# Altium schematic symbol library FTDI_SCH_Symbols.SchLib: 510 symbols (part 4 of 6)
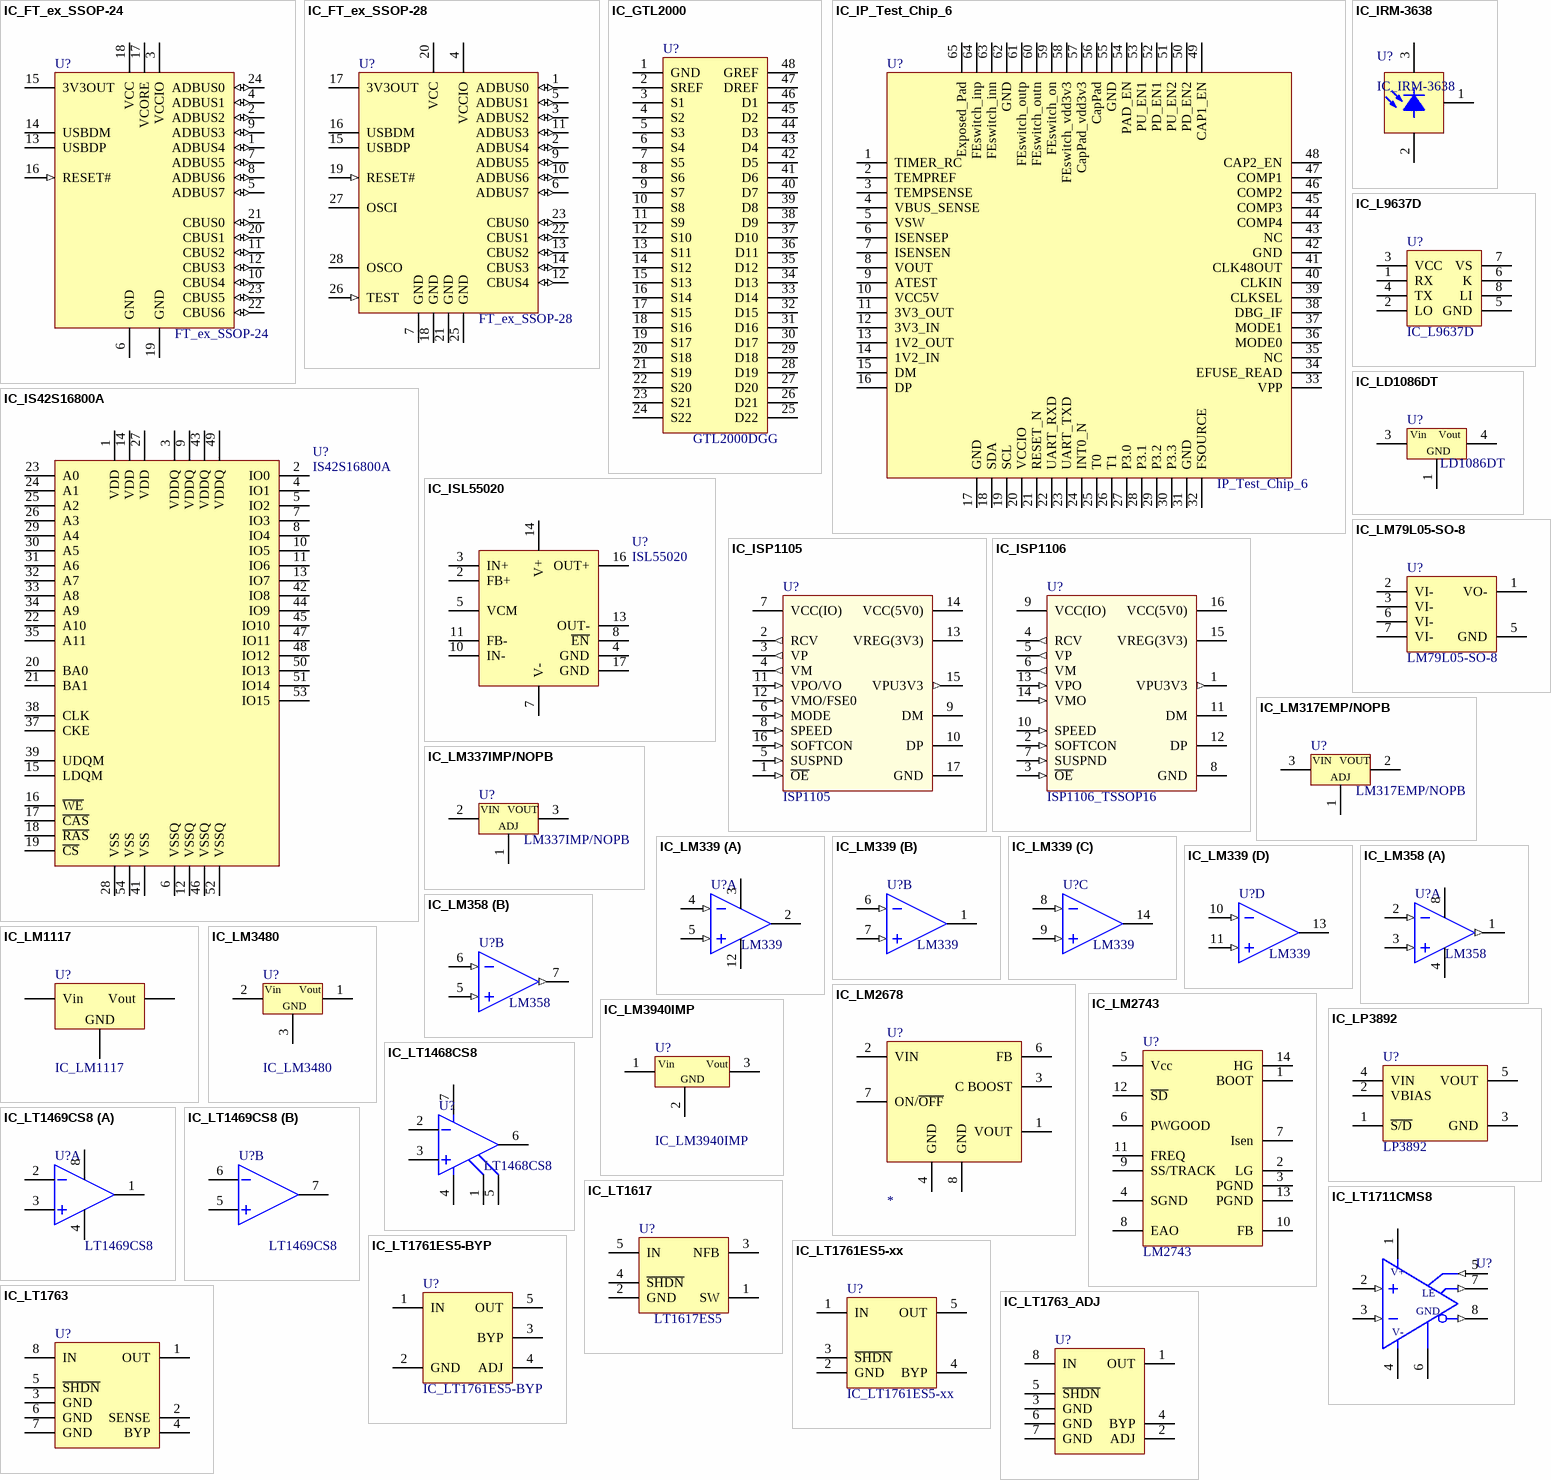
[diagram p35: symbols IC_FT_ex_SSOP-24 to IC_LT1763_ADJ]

## IC_IP_Test_Chip_6
designator U?, comment IP_Test_Chip_6
FTDI IP Test Chip 6
footprint SO-24N (SOIC, 24-Leads, Body 15.4x7.5mm, Pitch 1.27mm, IPC Medium Density)
footprint TSOP65P640X120-24N (TSOP, 24-Leads, Body 7.9x4.5mm (max), Pitch 0.65mm, IPC Medium Density)
pins: 1 TIMER_RC, 2 TEMPREF, 3 TEMPSENSE, 4 VBUS_SENSE, 5 VSW, 6 ISENSEP, 7 ISENSEN, 8 VOUT, 9 ATEST, 10 VCC5V, 11 3V3_OUT, 12 3V3_IN, 13 1V2_OUT, 14 1V2_IN, 15 DM, 16 DP, 17 GND, 18 SDA, 19 SCL, 20 VCCIO, 21 RESET_N, 22 UART_RXD, 23 UART_TXD, 24 INT0_N, 25 T0, 26 T1, 27 P3.0, 28 P3.1, 29 P3.2, 30 P3.3, 31 GND, 32 FSOURCE, 33 VPP, 34 EFUSE_READ, 35 NC, 36 MODE0, 37 MODE1, 38 DBG_IF, 39 CLKSEL, 40 CLKIN, 41 CLK48OUT, 42 GND, 43 NC, 44 COMP4, 45 COMP3, 46 COMP2, 47 COMP1, 48 CAP2_EN, 49 CAP1_EN, 50 PD_EN2, 51 PU_EN2, 52 PD_EN1, 53 PU_EN1, 54 PAD_EN, 55 GND, 56 CapPad, 57 CapPad_vdd3v3, 58 FEswitch_vdd3v3, 59 FEswitch_on, 60 FEswitch_outn, 61 FEswitch_outp, 62 GND, 63 FEswitch_inn, 64 FEswitch_inp, 65 Exposed_Pad

## IC_IRM-3638
designator U?
Infrared Remote Control Receiver; 38kHz
footprint IRM-3638 (Infrared remote control receiver)
pins: 1 OUT, 2 GND, 3 Vcc

## IC_IS42S16800A
designator U?, comment IS42S16800A
8 Meg x 16, 128-MBIT SYNCHRONOUS DRAM
footprint TSOP80P1180X120-54N (TSOP, 54-Leads, Body 22.4x10.3mm (max), Pitch 0.80mm, IPC Medium Density)
pins: 1 VDD, 2 IO0, 3 VDDQ, 4 IO1, 5 IO2, 6 VSSQ, 7 IO3, 8 IO4, 9 VDDQ, 10 IO5, 11 IO6, 12 VSSQ, 13 IO7, 14 VDD, 15 LDQM, 16 ~{WE}, 17 ~{CAS}, 18 ~{RAS}, 19 ~{CS}, 20 BA0, 21 BA1, 22 A10, 23 A0, 24 A1, 25 A2, 26 A3, 27 VDD, 28 VSS, 29 A4, 30 A5, 31 A6, 32 A7, 33 A8, 34 A9, 35 A11, 36 NC hidden, 37 CKE, 38 CLK, 39 UDQM, 40 NC hidden, 41 VSS, 42 IO8, 43 VDDQ, 44 IO9, 45 IO10, 46 VSSQ, 47 IO11, 48 IO12, 49 VDDQ, 50 IO13, 51 IO14, 52 VSSQ, 53 IO15, 54 VSS

## IC_ISL55020
designator U?, comment ISL55020
Wideband, Low Distortion, Differential  Amplifier
footprint QFN65P400X400X100-16M (QFN, 16-Leads, Body 4.0x4.0mm (max), Pitch 0.65mm, IPC Low Density)
pins: 2 FB+, 3 IN+, 4 GND, 5 VCM, 7 V-, 8 ~{EN}, 10 IN-, 11 FB-, 13 OUT-, 14 V+, 16 OUT+, 17 GND

## IC_ISP1105
designator U?, comment ISP1105
USB Transceiver
pins: 1 ~{OE} (in), 2 RCV (out), 3 VP (out), 4 VM (out), 5 SUSPND (in), 6 MODE (in), 7 VCC(IO) (power), 8 SPEED (in), 9 DM, 10 DP, 11 VPO/VO (in), 12 VMO/FSE0 (in), 13 VREG(3V3) (power), 14 VCC(5V0) (power), 15 VPU3V3 (out), 16 SOFTCON (in), 17 GND (power)

## IC_ISP1106
designator U?, comment ISP1106_TSSOP16
Advanced Universal Serial Bus transceiver; TSSOP-16
footprint TSSOP127P600-16N
pins: 1 VPU3V3 (out), 2 SOFTCON (in), 3 ~{OE} (in), 4 RCV (out), 5 VP (out), 6 VM (out), 7 SUSPND (in), 8 GND (power), 9 VCC(IO) (power), 10 SPEED (in), 11 DM, 12 DP, 13 VPO (in), 14 VMO (in), 15 VREG(3V3) (power), 16 VCC(5V0) (power)

## IC_L9637D
designator U?
ISO 9141 INTERFACE
footprint SO-8N (8-Pin Small Outline Integrated Circuit 1.27 mm Pitch, IPC Medium Density)
pins: 1 RX, 2 LO, 3 VCC, 4 TX, 5 GND, 6 K, 7 VS, 8 LI

## IC_LD1086DT
designator U?, comment LD1086DT
LDO Voltage Regulator; 1.5A; DPAK-3
footprint DPAK-3N (D-PAK, 3-Pads, Body 6.2x6.6mm (max), IPC Medium Density)
pins: 1 GND, 3 Vin, 4 Vout

## IC_LM79L05-SO-8
designator U?, comment LM79L05-SO-8
footprint SO-8_N (8-Pin Small Outline Integrated Circuit 1.27 mm Pitch, IPC Medium Density)
pins: 1 VO-, 2 VI-, 3 VI-, 4 NC hidden, 5 GND, 6 VI-, 7 VI-, 8 NC hidden

## IC_LM317EMP/NOPB
designator U?, comment LM317EMP/NOPB
3-Terminal Adjustable Positive Regulator; Manufacturer: National Semiconductor; Note: IC REG POSITIVE ADJ 1A SOT223
footprint SOT223P700X180-3N (SOT223, 4-Leads, Body 6.7x7.3mm (max), Pitch 2.30mm, IPC Medium Density)
pins: 1 ADJ, 2 Vout, 3 Vin

## IC_LM337IMP/NOPB
designator U?, comment LM337IMP/NOPB
3-Terminal Adjustable Negative Regulator; Manufacturer: National Semiconductor; Note: IC VREG NEGATIVE ADJ 1A SOT223
footprint SOT223P700X180-3N (SOT223, 4-Leads, Body 6.7x7.3mm (max), Pitch 2.30mm, IPC Medium Density)
pins: 1 ADJ, 2 Vin, 3 Vout

## IC_LM339
designator U?, comment LM339
Low power dual operational amplifier; Manufacturer: Analog Devices; ManufacturerPartNo: AD8033AR
footprint TSOP65P640X110-14N (TSOP, 14-Leads, Body 5.1x4.5mm (max), Pitch 0.65mm, IPC Medium Density)
part A pins: 2 OUT1 (oc), 3 VCC, 4 IN-1 (in), 5 IN+1 (in), 12 VSS
part B pins: 1 OUT2 (oc), 6 IN-2 (in), 7 IN+2 (in)
part C pins: 8 IN-3 (in), 9 IN+3 (in), 14 OUT3 (oc)
part D pins: 10 IN-4 (in), 11 IN+4 (in), 13 OUT4 (oc)

## IC_LM358
designator U?, comment LM358
Low power dual operational amplifier; Manufacturer: Analog Devices; ManufacturerPartNo: AD8033AR
footprint SO-8N (8-Pin Small Outline Integrated Circuit 1.27 mm Pitch, IPC Medium Density)
part A pins: 1 OUT1 (out), 2 IN-1 (in), 3 IN+1 (in), 4 VSS, 8 VCC
part B pins: 5 IN+2 (in), 6 IN-2 (in), 7 OUT2 (out)

## IC_LM1117
designator U?
0.8A Voltage Regulator
footprint SOT223P700X180-4N (SOT223, 4-Leads, Body 6.7x7.3mm (max), Pitch 2.30mm, IPC Medium Density)
footprint TO252P955X203-3N (D-PAK, 3-Pads, Body 6.3x6.2mm (max), IPC Medium Density); pin to pad 2>4
pins: 1 GND, 2 Vout, 3 Vin, 4 Vout hidden

## IC_LM2678
designator U?
SIMPLE SWITCHER® High Efficiency 5A Step-Down  Voltage Regulator
footprint TO-263-7 (TO-263-7pin SMT package)
footprint TO-263-7 (TO-263-7pin SMT package)
pins: 1 VOUT, 2 VIN, 3 C BOOST, 4 GND, 6 FB, 7 ON/~{OFF}, 8 GND

## IC_LM2743
designator U?, comment LM2743
Low Voltage N-Channel MOSFET Synchronous Buck  Regulator Controller
footprint TSSOP-14
pins: 1 BOOT, 2 LG, 3 PGND, 4 SGND, 5 Vcc, 6 PWGOOD, 7 Isen, 8 EAO, 9 SS/TRACK, 10 FB, 11 FREQ, 12 ~{SD}, 13 PGND, 14 HG

## IC_LM3480
designator U?
100 mA, SOT-23, Quasi Low-Dropout Linear Voltage  Regulator
footprint SOT23-3AL (SOT23 SMT Package)
pins: 1 Vout, 2 Vin, 3 GND

## IC_LM3940IMP
designator U?
1A Voltage Regulator
footprint SOT223P700X180-4N (SOT223, 4-Leads, Body 6.7x7.3mm (max), Pitch 2.30mm, IPC Medium Density)
footprint TO252P955X203-3N (D-PAK, 3-Pads, Body 6.3x6.2mm (max), IPC Medium Density); pin to pad 2>4 4>2
pins: 1 Vin, 2 GND, 3 Vout, 4 GND hidden to GND

## IC_LP3892
designator U?, comment LP3892
1.5A; LDO
footprint PSOP8
pins: 1 ~{S/D}, 2 VBIAS, 3 GND, 4 VIN, 5 VOUT

## IC_LT1468CS8
designator U?, comment LT1468CS8
90MHz, 22V/µs  16-Bit Accurate  Operational Amplifi er; Manufacturer: Linear Technology; Note: 4.5ns Single/Dual Supply  3V/5V Comparator with  Rail-to-Rail Output
footprint SO-8N (8-Pin Small Outline Integrated Circuit 1.27 mm Pitch, IPC Medium Density)
pins: 1 NULL, 2 +IN, 3 -IN, 4 VEE, 5 NULL, 6 OUT, 7 VCC, 8 DNC hidden

## IC_LT1469CS8
designator U?, comment LT1469CS8
Dual 90MHz, 22V/us  16-Bit Accurate Operational Amplifier; Manufacturer: Linear Technology
footprint SO-8N (8-Pin Small Outline Integrated Circuit 1.27 mm Pitch, IPC Medium Density)
part A pins: 1 OUTA, 2 -INA, 3 +INA, 4 V-, 8 V+
part B pins: 5 IN+B, 6 IN-B, 7 OUTB

## IC_LT1617
designator U?, comment LT1617ES5
Micropower Inverting DC/DC Converter in SOT-23
footprint SOT23-5AL (SOT23, 5-Leads, Body 2.9x1.6mm, Pitch 0.95mm, Lead Span 2.8mm)
pins: 1 SW, 2 GND, 3 NFB, 4 ~{SHDN}, 5 IN

## IC_LT1711CMS8
designator U?
Single, 4.5ns, 3V/5V/±5V,  Rail-to-Rail Comparator; Manufacturer: Analog Devices; ManufacturerPartNo: AD8033AR
footprint SOP65P400X130-8N (SOP, 8-Leads, Body 3.2x2.9mm (max), Pitch 0.65mm, IPC Medium Density)
pins: 1 V+ (power), 2 IN+ (in), 3 IN- (in), 4 V- (power), 5 LE (in), 6 GND (power), 7 Q (out), 8 ~{Q} (out)

## IC_LT1761ES5-BYP
designator U?
Adjustable output; 100mA; LDO Micropower  Regulator in SOT-23
footprint SOT23-5AL (SOT23, 5-Leads, Body 2.9x1.6mm, Pitch 0.95mm, Lead Span 2.8mm, IPC High Density)
pins: 1 IN, 2 GND (power), 3 BYP, 4 ADJ, 5 OUT

## IC_LT1761ES5-xx
designator U?
100mA; LDO Micropower  Regulators in SOT-23
footprint SOT23-5AL (SOT23, 5-Leads, Body 2.9x1.6mm, Pitch 0.95mm, Lead Span 2.8mm, IPC High Density)
pins: 1 IN, 2 GND (power), 3 ~{SHDN}, 4 BYP, 5 OUT

## IC_LT1763
designator U?
500mA; LDO Micropower  Regulator
footprint SO-8_N (8-Pin Small Outline Integrated Circuit 1.27 mm Pitch, IPC Medium Density)
pins: 1 OUT, 2 SENSE, 3 GND (power), 4 BYP, 5 ~{SHDN}, 6 GND (power), 7 GND (power), 8 IN

## IC_LT1763_ADJ
designator U?
500mA; LDO Micropower  Regulator
footprint SO-8_N (8-Pin Small Outline Integrated Circuit 1.27 mm Pitch, IPC Medium Density)
pins: 1 OUT, 2 ADJ, 3 GND (power), 4 BYP, 5 ~{SHDN}, 6 GND (power), 7 GND (power), 8 IN

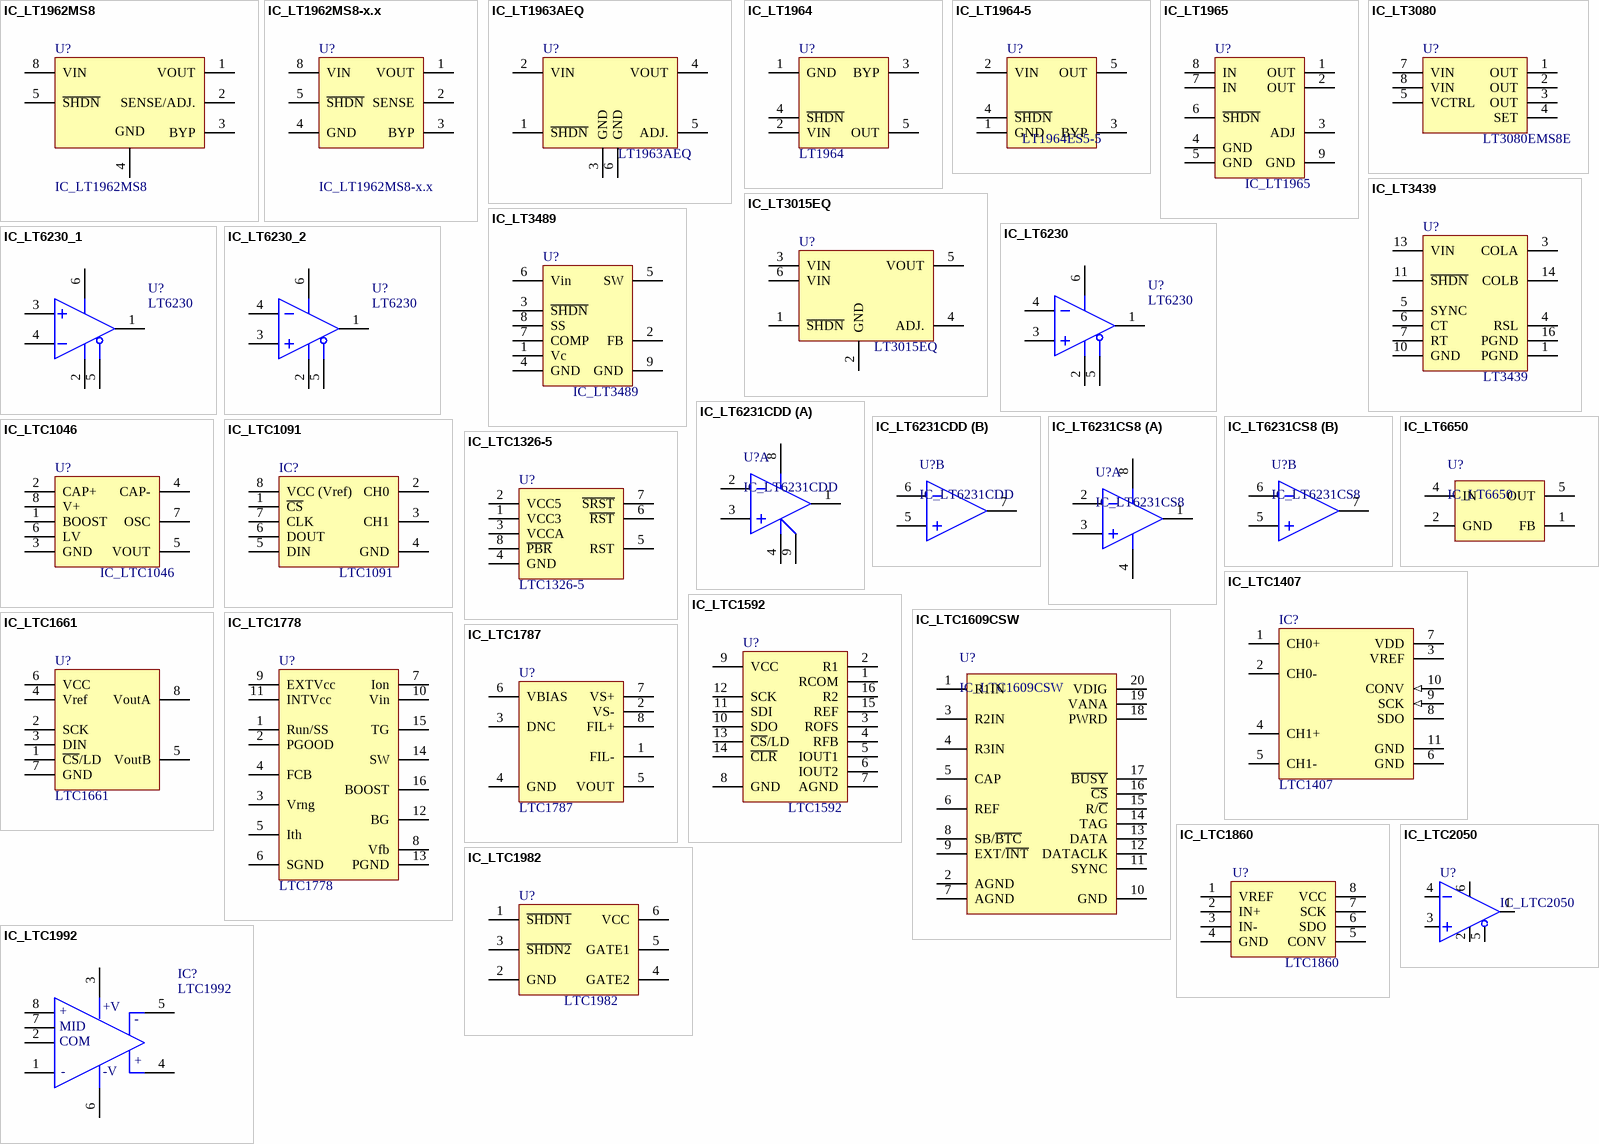
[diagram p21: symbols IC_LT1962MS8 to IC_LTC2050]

## IC_LT1962MS8
designator U?
Adjustable Output; 300mA, Low Noise,  Micropower  LDO Regulator
footprint MSOP65P490X110-8N (MSOP, 8-Leads, Body 3.1x3.1mm (max), Pitch 0.65mm, IPC Medium Density)
pins: 1 VOUT, 2 SENSE/ADJ. (power), 3 BYP, 4 GND, 5 ~{SHDN}, 6 NC hidden, 7 NC hidden, 8 VIN

## IC_LT1962MS8-x.x
designator U?
300mA, Low Noise,  Micropower  LDO Regulators
footprint MSOP65P490X110-8N (MSOP, 8-Leads, Body 3.1x3.1mm (max), Pitch 0.65mm, IPC Medium Density)
pins: 1 VOUT, 2 SENSE (power), 3 BYP, 4 GND, 5 ~{SHDN}, 6 NC hidden, 7 NC hidden, 8 VIN

## IC_LT1963AEQ
designator U?, comment LT1963AEQ
1.5A, Low Noise,  Fast Transient Response  LDO Regulator
footprint DPAK-3N (D-PAK, 3-Pads, Body 6.2x6.6mm (max), IPC Medium Density)
pins: 1 ~{SHDN}, 2 VIN, 3 GND, 4 VOUT, 5 ADJ. (power), 6 GND

## IC_LT1964
designator U?, comment LT1964
200mA, Low Noise,  Low Dropout Negative  Micropower Regulator in ThinSOT
footprint SOT23-5AL (SOT23, 5-Leads, Body 2.9x1.6mm, Pitch 0.95mm, Lead Span 2.8mm)
pins: 1 GND, 2 VIN (power), 3 BYP, 4 ~{SHDN}, 5 OUT

## IC_LT1964-5
designator U?, comment LT1964ES5-5
200mA, Low Noise,  Low Dropout Negative  Micropower Regulator
footprint SOT23-5AL (SOT23, 5-Leads, Body 2.9x1.6mm, Pitch 0.95mm, Lead Span 2.8mm)
pins: 1 GND, 2 VIN, 3 BYP, 4 ~{SHDN}, 5 OUT

## IC_LT1965
designator U?
pins: 1 OUT, 2 OUT, 3 ADJ, 4 GND, 5 GND, 6 ~{SHDN}, 7 IN, 8 IN, 9 GND

## IC_LT3015EQ
designator U?, comment LT3015EQ
1.5A, Low Noise,  Negative Linear Regulator  with Precision Current Limit
footprint DPAK-3N (D-PAK, 3-Pads, Body 6.2x6.6mm (max), IPC Medium Density)
pins: 1 ~{SHDN}, 2 GND, 3 VIN, 4 ADJ. (power), 5 VOUT, 6 VIN

## IC_LT3080
designator U?, comment LT3080EMS8E
Adjustable,1.1A, Single Resistor, Low Dropout Regulator
footprint MSOP65P510X110_HS-8N (MSOP, 8-Leads, Body 3.1x3.1mm (max), Pitch 0.65mm, IPC Medium Density)
pins: 1 OUT (power), 2 OUT (power), 3 OUT (power), 4 SET, 5 VCTRL (power), 6 NC hidden, 7 VIN (power), 8 VIN (power), 9 OUT

## IC_LT3439
designator U?, comment LT3439
Slew Rate Controlled  Ultralow Noise1A Isolated  DC/DC Transformer Driver
footprint TSSOP65P640X120-16N (TSOP, 16-Leads, Body 5.1x4.5mm (max), Pitch 0.65mm, IPC Medium Density)
pins: 1 PGND, 2 NC hidden, 3 COLA, 4 RSL, 5 SYNC, 6 CT, 7 RT, 8 NC hidden, 9 NC hidden, 10 GND, 11 ~{SHDN}, 12 NC hidden, 13 VIN, 14 COLB, 15 NC hidden, 16 PGND

## IC_LT3489
designator U?
pins: 1 Vc, 2 FB, 3 ~{SHDN}, 4 GND, 5 SW, 6 Vin, 7 COMP, 8 SS, 9 GND

## IC_LT6230
designator U?, comment LT6230
215MHz, Rail-to-Rail Output, 3.5mA Op Amp Family
footprint SOT23-6N (SOT23, 6-Leads, Body 3.0x3.0mm (max), Pitch 0.95mm, IPC Medium Density)
pins: 1 OUT, 2 V-, 3 IN+, 4 IN-, 5 ~{EN}, 6 V+

## IC_LT6230_1
designator U?, comment LT6230
215MHz, Rail-to-Rail Output, 3.5mA Op Amp Family
footprint SOT23-6N (SOT23, 6-Leads, Body 3.0x3.0mm (max), Pitch 0.95mm, IPC Medium Density)
pins: 1 OUT, 2 V-, 3 IN+, 4 IN-, 5 ~{EN}, 6 V+

## IC_LT6230_2
designator U?, comment LT6230
215MHz, Rail-to-Rail Output, 3.5mA Op Amp Family
footprint SOT23-6N (SOT23, 6-Leads, Body 3.0x3.0mm (max), Pitch 0.95mm, IPC Medium Density)
pins: 1 OUT, 2 V-, 3 IN+, 4 IN-, 5 ~{EN}, 6 V+

## IC_LT6231CDD
designator U?
215MHz, Rail-to-Rail Output, 3.5mA Op Amp Family
footprint QFN50P300X300X85-8N (QFN, 8-Leads, Body 3.1x3.1mm (max), Pitch 0.50mm, IPC Medium Density)
part A pins: 1 OUTA, 2 -IN A, 3 +IN A, 4 V-, 8 V+, 9 PAD
part B pins: 5 +IN B, 6 -IN B, 7 OUT B

## IC_LT6231CS8
designator U?
215MHz, Rail-to-Rail Output, 3.5mA Op Amp Family
footprint QFN50P300X300X85-8N (QFN, 8-Leads, Body 3.1x3.1mm (max), Pitch 0.50mm, IPC Medium Density)
part A pins: 1 OUTA, 2 -IN A, 3 +IN A, 4 V-, 8 V+
part B pins: 5 +IN B, 6 -IN B, 7 OUT B

## IC_LT6650
designator U?
Micropower, 400mV  Reference with Rail-to-Rail  Buffer Amplifier in SOT-23
footprint SOT23-5AL (SOT23, 5-Leads, Body 2.9x1.6mm, Pitch 0.95mm, Lead Span 2.8mm)
pins: 1 FB, 2 GND, 3 NC hidden, 4 IN, 5 OUT

## IC_LTC1046
designator U?
50mA monolithic CMOS switched  capacitor voltage converter
footprint SO-8_N (8-Pin Small Outline Integrated Circuit 1.27 mm Pitch, IPC Medium Density)
pins: 1 BOOST (power), 2 CAP+ (power), 3 GND (power), 4 CAP- (power), 5 VOUT (power), 6 LV (power), 7 OSC (power), 8 V+ (power)

## IC_LTC1091
designator IC?, comment LTC1091
Serial 12-Bit/14-Bit, 3Msps  Simultaneous Sampling  ADCs with Shutdown
footprint SO-8N (8-Pin Small Outline Integrated Circuit 1.27 mm Pitch, IPC Medium Density)
pins: 1 ~{CS}, 2 CH0, 3 CH1, 4 GND, 5 DIN, 6 DOUT (power), 7 CLK (power), 8 VCC (Vref) (oc)

## IC_LTC1326-5
designator U?, comment LTC1326-5
Tripple Voltage Controller
pins: 1 VCC3, 2 VCC5, 3 VCCA, 4 GND, 5 RST, 6 ~{RST}, 7 ~{SRST}, 8 ~{PBR}

## IC_LTC1407
designator IC?, comment LTC1407
Serial 12-Bit/14-Bit, 3Msps  Simultaneous Sampling  ADCs with Shutdown
footprint SOP127P600-8N_w_thermal_pad
pins: 1 CH0+, 2 CH0-, 3 VREF, 4 CH1+, 5 CH1-, 6 GND (power), 7 VDD (power), 8 SDO (oc), 9 SCK (in), 10 CONV (in), 11 GND (power)

## IC_LTC1592
designator U?, comment LTC1592
16-Bit SoftSpan DAC  with Programmable Output Range
footprint SSOP63P600X175-16N (SOP, 16-Leads, Body 5.0x4.0mm (max), Pitch 0.63mm, IPC Medium Density)
pins: 1 RCOM, 2 R1, 3 ROFS, 4 RFB, 5 IOUT1, 6 IOUT2, 7 AGND, 8 GND, 9 VCC, 10 SDO, 11 SDI, 12 SCK, 13 ~{CS}/LD, 14 ~{CLR}, 15 REF, 16 R2

## IC_LTC1609CSW
designator U?
16-Bit, 200ksps, Serial ADC  with Multiple Input Ranges
pins: 1 R1IN, 2 AGND, 3 R2IN, 4 R3IN, 5 CAP, 6 REF, 7 AGND, 8 SB/~{BTC}, 9 EXT/~{INT}, 10 GND, 11 SYNC, 12 DATACLK, 13 DATA, 14 TAG, 15 R/~{C}, 16 ~{CS}, 17 ~{BUSY}, 18 PWRD, 19 VANA, 20 VDIG

## IC_LTC1661
designator U?, comment LTC1661
Micropower Dual  10-Bit DAC in MSOP
footprint MSOP65P490X96-8N (MSOP, 8-Leads, Body 3.1x3.1mm (max), Pitch 0.65mm, IPC Medium Density)
pins: 1 ~{CS}/LD, 2 SCK, 3 DIN, 4 Vref, 5 VoutB, 6 VCC, 7 GND, 8 VoutA

## IC_LTC1778
designator U?, comment LTC1778
Wide Operating Range,  No RSENSE (TM) Step-Down Controller
footprint SOP63P600X173-16N (SOP, 16-Leads, Body 5.0x4.0mm (max), Pitch 0.63mm, IPC Medium Density)
pins: 1 Run/SS, 2 PGOOD, 3 Vrng, 4 FCB, 5 Ith, 6 SGND, 7 Ion, 8 Vfb, 9 EXTVcc, 10 Vin, 11 INTVcc, 12 BG, 13 PGND, 14 SW, 15 TG, 16 BOOST

## IC_LTC1787
designator U?, comment LTC1787
Precision, High Side  Current Sense Amplifiers
footprint MSOP-08
pins: 1 FIL-, 2 VS-, 3 DNC, 4 GND, 5 VOUT, 6 VBIAS, 7 VS+, 8 FIL+

## IC_LTC1860
designator U?, comment LTC1860
Serial 12-Bit/14-Bit, 3.5Msps  Sampling ADCs with Shutdown
pins: 1 VREF, 2 IN+, 3 IN-, 4 GND, 5 CONV, 6 SDO, 7 SCK, 8 VCC

## IC_LTC1982
designator U?, comment LTC1982
Dual Micropower High Side Switch Controller in SOT-23
footprint SOT23-6N (SOT23, 6-Leads, Body 3.0x3.0mm (max), Pitch 0.95mm, IPC Medium Density)
pins: 1 ~{SHDN1}, 2 GND, 3 ~{SHDN2}, 4 GATE2, 5 GATE1, 6 VCC

## IC_LTC1992
designator IC?, comment LTC1992
Low Power, Fully Differential  Input/Output  Amplifier/Driver Family
footprint SOT23-8AL (SOT23 8-PIN 0.65mm PITCH)
pins: 1 IN-, 2 VCOM, 3 +VS, 4 OUT+, 5 OUT-, 6 -VS, 7 VMID, 8 IN+

## IC_LTC2050
designator U?
Zero-Drift Operational Amplifier in SOT-23
footprint SOT23-6N (SOT23, 6-Leads, Body 3.0x3.0mm (max), Pitch 0.95mm, IPC Medium Density)
pins: 1 OUT, 2 V-, 3 IN+, 4 IN-, 5 ~{SHDN} (power), 6 V+

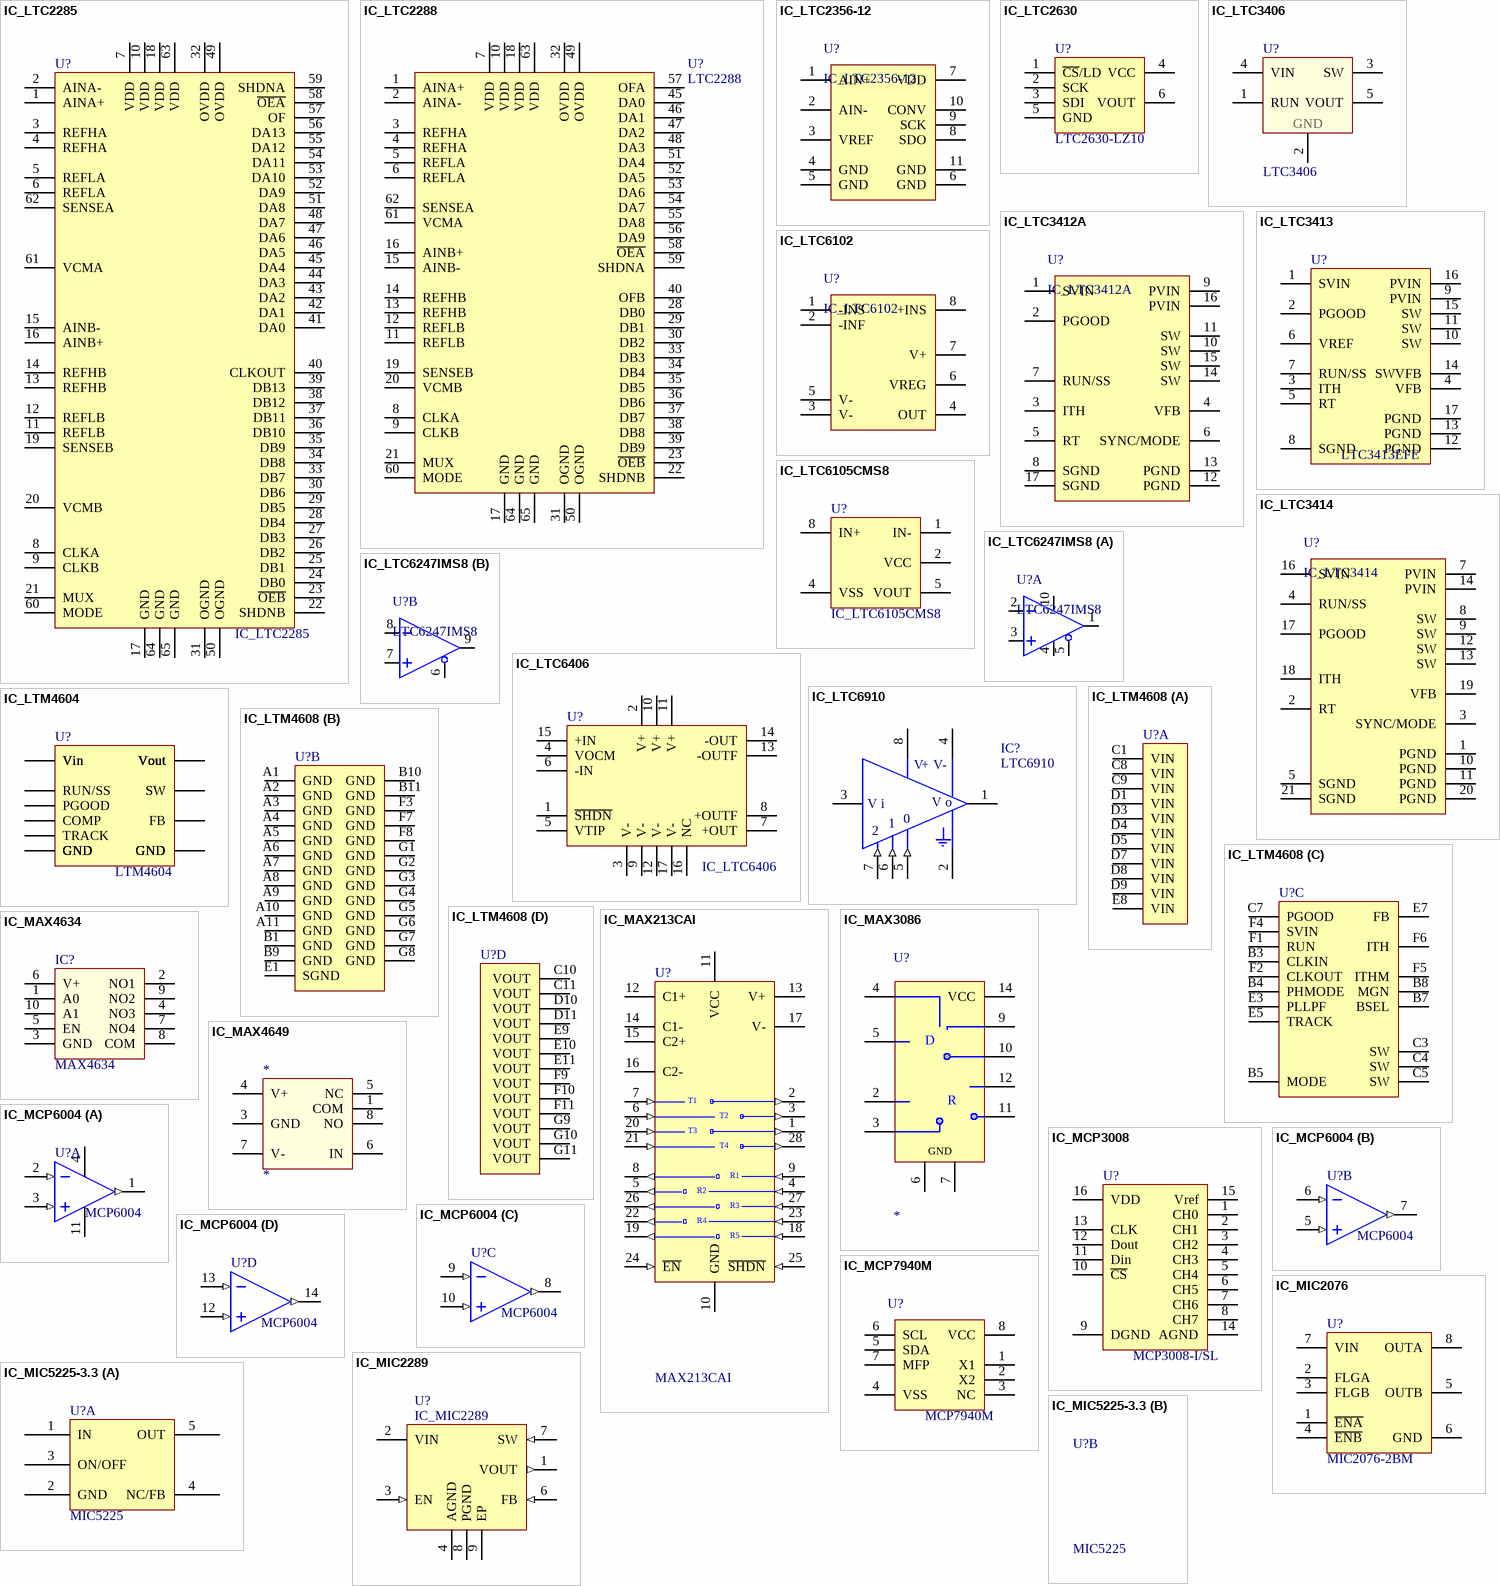
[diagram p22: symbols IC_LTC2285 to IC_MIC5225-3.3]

## IC_LTC2285
designator U?
Dual 14-Bit, 125Msps Low Power 3V ADC
footprint QFN50P900X900X80-64M (QFN, 64-Leads, Body 9.1x9.1mm (max), Pitch 0.50mm, IPC Low Density)
pins: 1 AINA+, 2 AINA-, 3 REFHA, 4 REFHA, 5 REFLA, 6 REFLA, 7 VDD, 8 CLKA, 9 CLKB, 10 VDD, 11 REFLB, 12 REFLB, 13 REFHB, 14 REFHB, 15 AINB-, 16 AINB+, 17 GND, 18 VDD, 19 SENSEB, 20 VCMB, 21 MUX, 22 SHDNB, 23 ~{OEB}, 24 DB0, 25 DB1, 26 DB2, 27 DB3, 28 DB4, 29 DB5, 30 DB6, 31 OGND, 32 OVDD, 33 DB7, 34 DB8, 35 DB9, 36 DB10, 37 DB11, 38 DB12, 39 DB13, 40 CLKOUT, 41 DA0, 42 DA1, 43 DA2, 44 DA3, 45 DA4, 46 DA5, 47 DA6, 48 DA7, 49 OVDD, 50 OGND, 51 DA8, 52 DA9, 53 DA10, 54 DA11, 55 DA12, 56 DA13, 57 OF, 58 ~{OEA}, 59 SHDNA, 60 MODE, 61 VCMA, 62 SENSEA, 63 VDD, 64 GND, 65 GND

## IC_LTC2288
designator U?, comment LTC2288
Dual 10-Bit, 65/40/25Msps  Low Noise 3V ADC
footprint QFN50P900X900X80-64M (QFN, 64-Leads, Body 9.1x9.1mm (max), Pitch 0.50mm, IPC Low Density)
pins: 1 AINA+, 2 AINA-, 3 REFHA, 4 REFHA, 5 REFLA, 6 REFLA, 7 VDD, 8 CLKA, 9 CLKB, 10 VDD, 11 REFLB, 12 REFLB, 13 REFHB, 14 REFHB, 15 AINB-, 16 AINB+, 17 GND, 18 VDD, 19 SENSEB, 20 VCMB, 21 MUX, 22 SHDNB, 23 ~{OEB}, 24 NC hidden, 25 NC hidden, 26 NC hidden, 27 NC hidden, 28 DB0, 29 DB1, 30 DB2, 31 OGND, 32 OVDD, 33 DB3, 34 DB4, 35 DB5, 36 DB6, 37 DB7, 38 DB8, 39 DB9, 40 OFB, 41 NC hidden, 42 NC hidden, 43 NC hidden, 44 NC hidden, 45 DA0, 46 DA1, 47 DA2, 48 DA3, 49 OVDD, 50 OGND, 51 DA4, 52 DA5, 53 DA6, 54 DA7, 55 DA8, 56 DA9, 57 OFA, 58 ~{OEA}, 59 SHDNA, 60 MODE, 61 VCMA, 62 SENSEA, 63 VDD, 64 GND, 65 GND

## IC_LTC2356-12
designator U?
Serial 12-Bit/14-Bit, 3.5Msps  Sampling ADCs with Shutdown
pins: 1 AIN+, 2 AIN-, 3 VREF, 4 GND, 5 GND, 6 GND, 7 VDD, 8 SDO, 9 SCK, 10 CONV, 11 GND

## IC_LTC2630
designator U?, comment LTC2630-LZ10
Single 10-Bit  Rail-to- Rail DACs with 10ppm/°C  Reference in SC70
footprint SC70-0.65mm_pitch-6N (SC70, 6-Leads, Body 2.2x2.4mm (max), Pitch 0.65mm, IPC Medium Density)
pins: 1 ~{CS}/LD, 2 SCK, 3 SDI, 4 VCC, 5 GND, 6 VOUT

## IC_LTC3406
designator U?, comment LTC3406
1.5MHz, 600mA  Synchronous Step-Down  Regulator in ThinSOT
footprint SOT23-5AL (SOT23, 5-Leads, Body 2.9x1.6mm, Pitch 0.95mm, Lead Span 2.8mm)
pins: 1 RUN, 2 GND, 3 SW, 4 VIN, 5 VOUT

## IC_LTC3412A
designator U?
3A, 4MHz, Monolithic  Synchronous Step-Down Regulator
pins: 1 SVIN, 2 PGOOD, 3 ITH, 4 VFB, 5 RT, 6 SYNC/MODE, 7 RUN/SS, 8 SGND, 9 PVIN, 10 SW, 11 SW, 12 PGND, 13 PGND, 14 SW, 15 SW, 16 PVIN, 17 SGND

## IC_LTC3413
designator U?, comment LTC3413EFE
3A, 2MHz Monolithic  Synchronous Regulator for  DDR/QDR Memory Termination
footprint TSSOP65P640X110_HS-16N (TSOP, 16-Leads, Body 5.1x4.5mm (max), Pitch 0.65mm, IPC Medium Density)
pins: 1 SVIN (power), 2 PGOOD (power), 3 ITH (power), 4 VFB (power), 5 RT (power), 6 VREF (power), 7 RUN/SS (power), 8 SGND (power), 9 PVIN (power), 10 SW (power), 11 SW (power), 12 PGND (power), 13 PGND (power), 14 SWVFB (power), 15 SW (power), 16 PVIN (power), 17 PGND (power)

## IC_LTC3414
designator U?
4A, 4MHz, Monolithic  Synchronous Step-Down Regulator
pins: 1 PGND, 2 RT, 3 SYNC/MODE, 4 RUN/SS, 5 SGND, 6 NC hidden, 7 PVIN, 8 SW, 9 SW, 10 PGND, 11 PGND, 12 SW, 13 SW, 14 PVIN, 15 NC hidden, 16 SVIN, 17 PGOOD, 18 ITH, 19 VFB, 20 PGND, 21 SGND

## IC_LTC6102
designator U?
Precision Zero Drift Current Sense Amplifier
pins: 1 -INS, 2 -INF, 3 V-, 4 OUT, 5 V-, 6 VREG, 7 V+, 8 +INS

## IC_LTC6105CMS8
designator U?
Precision, Extended Input Range Current Sense Amplifier, Linear Technology
pins: 1 IN- (power), 2 VCC (power), 3 NC (power) hidden, 4 VSS (power), 5 VOUT (power), 6 NC (power) hidden, 7 NC (power) hidden, 8 IN+ (power)

## IC_LTC6247IMS8
designator U?, comment LTC6247IMS8
180MHz, 1mA Power  Efficient Rail-to-Rail  I/O Op Amps
footprint MSOP50P490X120-10N (MSOP, 10-Leads, Body 3.1x3.1mm (max), Pitch 0.50mm, IPC Medium Density)
part A pins: 1 OUTA, 2 INA-, 3 INA+, 4 V-, 5 ~{SHDNA} (power), 10 V+
part B pins: 6 ~{SHDNB} (power), 7 INB+, 8 INB-, 9 OUTB

## IC_LTC6406
designator U?
3GHz, Low Noise, Rail-to-Rail Input Differential Amplifier/Driver
pins: 1 ~{SHDN} (power), 2 V+ (power), 3 V- (power), 4 VOCM (power), 5 VTIP (power), 6 -IN (power), 7 +OUT (power), 8 +OUTF (power), 9 V- (power), 10 V+ (power), 11 V+ (power), 12 V- (power), 13 -OUTF (power), 14 -OUT (power), 15 +IN (power), 16 NC (power), 17 V- (power)

## IC_LTC6910
designator IC?, comment LTC6910
Digitally Controlled  Programmable  Gain Amplifiers in SOT-23
footprint SOT23-8AL (SOT23 8-PIN 0.65mm PITCH)
pins: 1 VOUT, 2 AGND (power), 3 VIN, 4 V- (power), 5 G0 (in), 6 G1 (in), 7 G2 (in), 8 V+ (power)

## IC_LTM4604
designator U?, comment LTM4604
footprint LGA1500X900X245 (uModule, LGA, 77-Leads, Body 15.0x9.0mm,  Pitch 1.27mm, Linear Technology)
pins: A1 GND, A2 GND, A3 GND, A4 GND, A5 GND, A6 GND, A7 GND, A8 GND, A9 GND, A10 GND, A11 GND, B1 Vin, B3 SW, B4 SW, B6 GND, B7 GND, B8 GND, B9 GND, B10 GND, B11 GND, C1 Vin, C3 Vin, C4 Vin, C5 Vin, C6 Vin, C7 Vin, C8 GND, C9 GND, C10 GND, C11 GND, D1 RUN/SS, D7 Vin, D8 Vout, D9 Vout, D10 Vout, D11 Vout, E1 TRACK, E4 GND, E5 GND, E6 Vin, E7 Vin, E8 Vout, E9 Vout, E10 Vout, E11 Vout, F1 PGOOD, F3 GND, F4 GND, F5 GND, F6 Vout, F7 Vout, F8 Vout, F9 Vout, F10 Vout, F11 Vout, G1 COMP, G2 FB, G3 GND, G4 GND, G5 GND, G6 Vout, G7 Vout, G8 Vout, G9 Vout, G10 Vout, G11 Vout

## IC_LTM4608
designator U?
Low VIN, 8A DC/DC  uModule with Tracking, Margining,  and Frequency Synchronization
part A pins: C1 VIN, C8 VIN, C9 VIN, D1 VIN, D3 VIN, D4 VIN, D5 VIN, D7 VIN, D8 VIN, D9 VIN, E8 VIN
part B pins: A1 GND, A2 GND, A3 GND, A4 GND, A5 GND, A6 GND, A7 GND, A8 GND, A9 GND, A10 GND, A11 GND, B1 GND, B9 GND, B10 GND, B11 GND, E1 SGND, F3 GND, F7 GND, F8 GND, G1 GND, G2 GND, G3 GND, G4 GND, G5 GND, G6 GND, G7 GND, G8 GND
part C pins: B3 CLKIN, B4 PHMODE, B5 MODE, B7 BSEL, B8 MGN, C3 SW, C4 SW, C5 SW, C7 PGOOD, E3 PLLPF, E5 TRACK, E7 FB, F1 RUN, F2 CLKOUT, F4 SVIN, F5 ITHM, F6 ITH
part D pins: C10 VOUT, C11 VOUT, D10 VOUT, D11 VOUT, E9 VOUT, E10 VOUT, E11 VOUT, F9 VOUT, F10 VOUT, F11 VOUT, G9 VOUT, G10 VOUT, G11 VOUT

## IC_MAX213CAI
designator U?, comment MAX213CAI
+5V RS-232 Transceiver with 0.1µF External Capacitor; Note: Pins 18, 19, 22 and 23 are active in SHUTDOWN.
footprint SSOP28 (SSOP; 28 Leads; Body Width 5.3 mm; Pitch 0.65 mm)
3D model SSOP28 (SSOP; 28 Leads; Body Width 5.3 mm; Pitch 0.65 mm)
pins: 1 T3OUT (out), 2 T1OUT (out), 3 T2OUT (out), 4 R2IN (in), 5 R2OUT (out), 6 T2IN (in), 7 T1IN (in), 8 R1OUT (out), 9 R1IN (in), 10 GND (power), 11 VCC (power), 12 C1+, 13 V+ (power), 14 C1-, 15 C2+, 16 C2-, 17 V- (power), 18 R5IN (in), 19 R5OUT (out), 20 T3IN (in), 21 T4IN (in), 22 R4OUT (out), 23 R4IN (in), 24 ~{EN} (in), 25 ~{SHDN} (in), 26 R3OUT (out), 27 R3IN (in), 28 T4OUT (out)

## IC_MAX3086
designator U?
RS422 Transceiver
footprint SO-14_N (14-Pin Small Outline Integrated Circuit 1.27 mm Pitch, IPC Medium Density)
pins: 1 NC hidden, 2 RO, 3 ~{RE}, 4 DE, 5 DI, 6 GND, 7 GND, 8 NC hidden, 9 Y, 10 Z, 11 B, 12 A, 13 NC hidden, 14 VCC

## IC_MAX4634
designator IC?, comment MAX4634
Fast, Low-Voltage, 4 Ohm,  4-Channel CMOS Analog Multiplexer
footprint TSSOP50P490X110-10N (TSSOP, 10-Leads, Body 3.0x3.0mm (max), Pitch 0.50mm, IPC Medium Density)
pins: 1 A0, 2 NO1, 3 GND, 4 NO3, 5 EN, 6 V+, 7 NO4, 8 COM, 9 NO2, 10 A1

## IC_MAX4649
designator *
pins: 1 COM, 2 NC hidden, 3 GND, 4 V+, 5 NC, 6 IN, 7 V-, 8 NO

## IC_MCP3008
designator U?, comment MCP3008-I/SL
2.7V 8-Channel 10-Bit A/D Converter  with SPI Serial Interface
footprint SO-16N (16-Pin Small Outline Integrated Circuit 1.27 mm Pitch, IPC Medium Density)
pins: 1 CH0, 2 CH1, 3 CH2, 4 CH3, 5 CH4, 6 CH5, 7 CH6, 8 CH7, 9 DGND, 10 ~{CS}, 11 Din, 12 Dout, 13 CLK, 14 AGND, 15 Vref, 16 VDD

## IC_MCP6004
designator U?, comment MCP6004
IC OPAMP GP 1MHZ RRO 14SOIC; Manufacturer: Microchip Technology; ManufacturerPartNo: MCP6004-I/SL
footprint TSOP65P640X110-14N (TSOP, 14-Leads, Body 5.1x4.5mm (max), Pitch 0.65mm, IPC Medium Density)
part A pins: 1 OUT1 (out), 2 IN-1 (in), 3 IN+1 (in), 4 VDD, 11 VSS
part B pins: 5 IN+2 (in), 6 IN-2 (in), 7 OUT2 (out)
part C pins: 8 OUT3 (out), 9 IN-3 (in), 10 IN+3 (in)
part D pins: 12 IN+4 (in), 13 IN-4 (in), 14 OUT4 (out)

## IC_MCP7940M
designator U?, comment MCP7940M
Low-Cost I2C Real-Time Clock/Calendar with SRAM
pins: 1 X1, 2 X2, 3 NC, 4 VSS, 5 SDA, 6 SCL, 7 MFP, 8 VCC

## IC_MIC2076
designator U?, comment MIC2076-2BM
USB Power distribution switch; 500mA
footprint SO-8_N (8-Pin Small Outline Integrated Circuit 1.27 mm Pitch, IPC Medium Density)
pins: 1 ~{ENA}, 2 FLGA, 3 FLGB, 4 ~{ENB}, 5 OUTB, 6 GND, 7 VIN, 8 OUTA

## IC_MIC2289
designator U?
White LED Driver; Manufacturer: Micrel Inc; ManufacturePartNo: MIC2289-34YML TR; Value: MIC2289-34; Note: IC LED DRIVER WHITE BCKLGT 8-MLF
footprint MLF8
pins: 1 VOUT (out), 2 VIN (power), 3 EN (in), 4 AGND (power), 5 NC hidden, 6 FB (in), 7 SW (in), 8 PGND (power), 9 EP

## IC_MIC5225-3.3
designator U?, comment MIC5225
part A pins: 1 IN, 2 GND, 3 ON/OFF, 4 NC/FB, 5 OUT

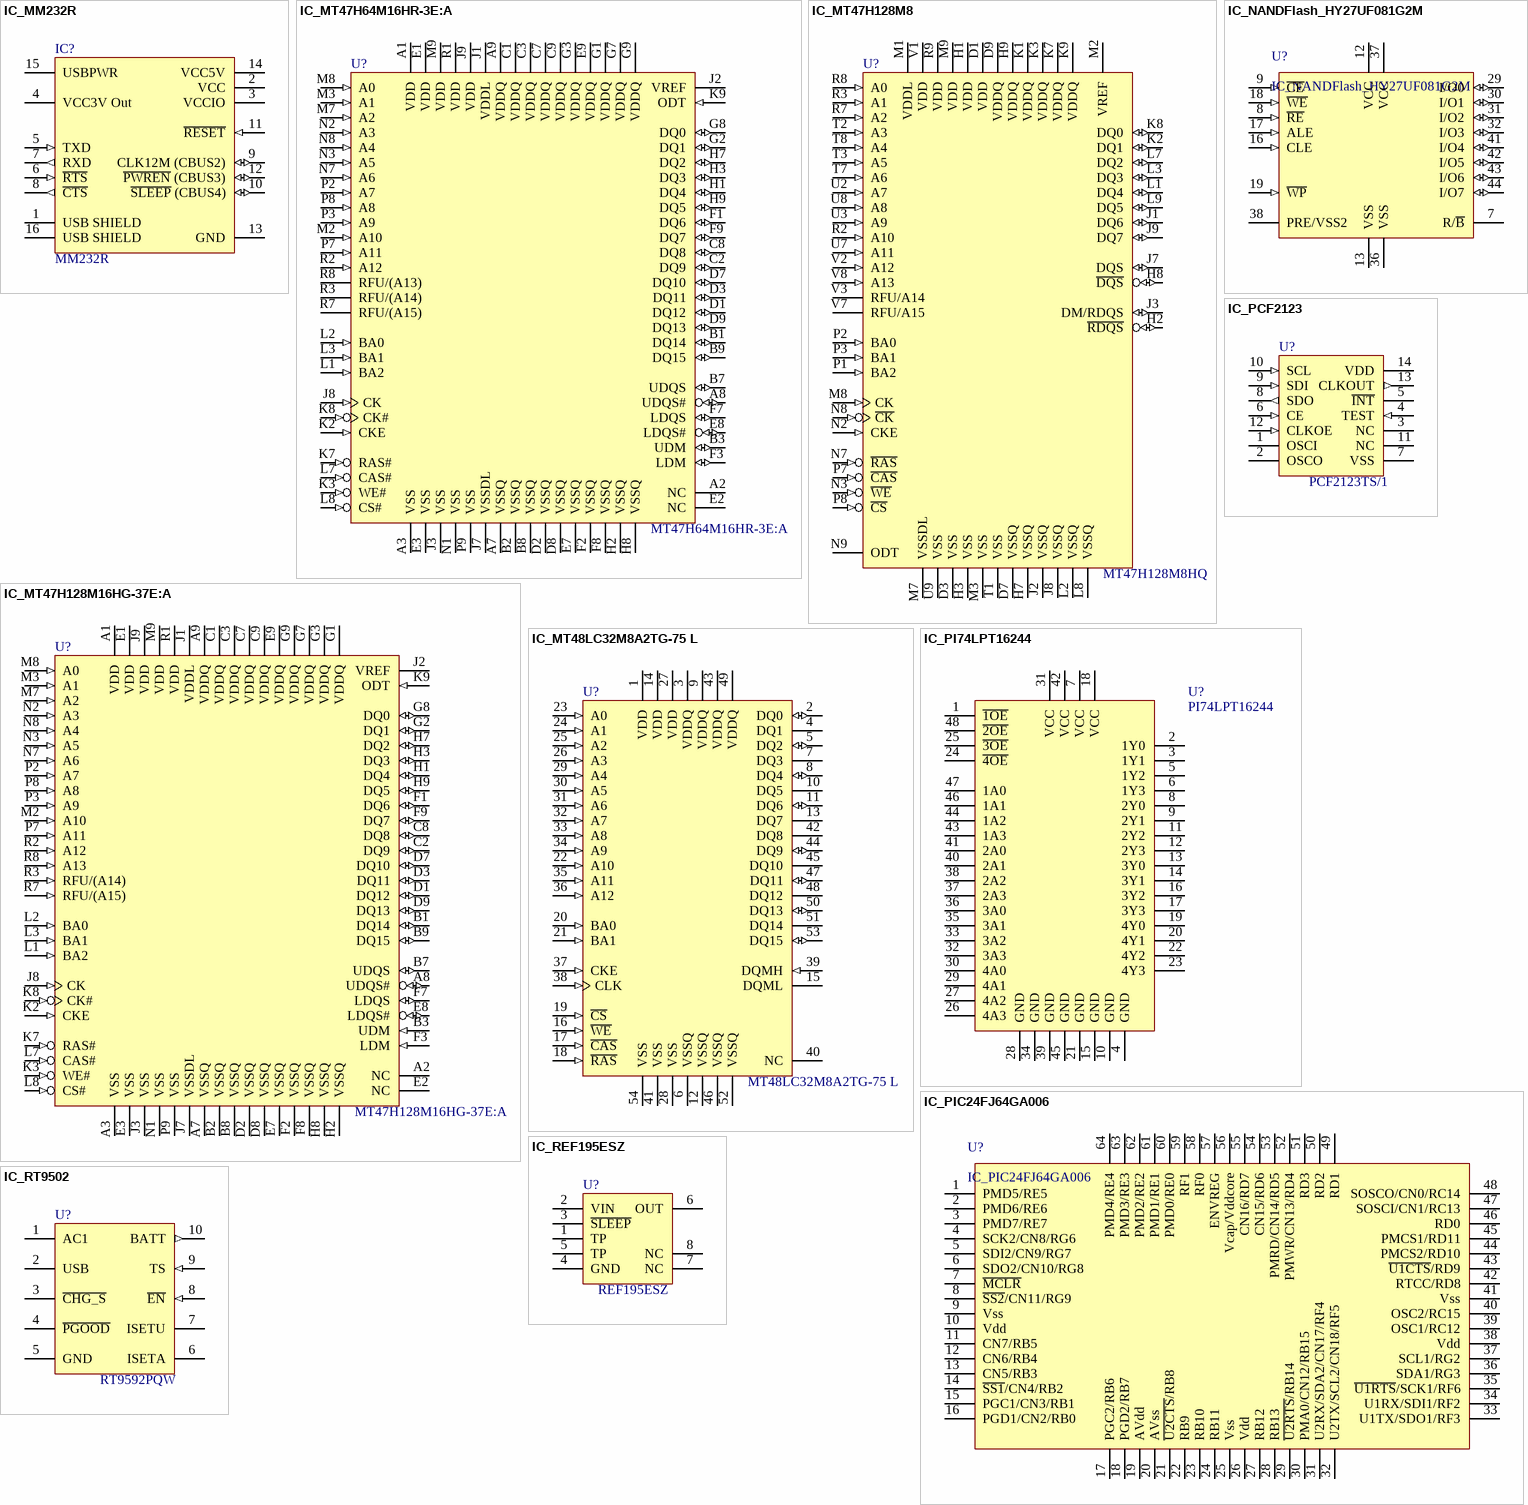
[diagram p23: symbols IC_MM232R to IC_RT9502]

## IC_MM232R
designator IC?, comment MM232R
FTDI MM232R module
footprint MM232 (FDTI's MM232R module)
pins: 1 USB SHIELD, 2 VCC (power), 3 VCCIO (power), 4 VCC3V Out (power), 5 TXD (in), 6 ~{RTS} (in), 7 RXD (out), 8 ~{CTS} (out), 9 CLK12M (CBUS2) (io), 10 ~{SLEEP} (CBUS4) (io), 11 ~{RESET} (in), 12 ~{PWREN} (CBUS3) (io), 13 GND (power), 14 VCC5V (power), 15 USBPWR (power), 16 USB SHIELD

## IC_MT47H64M16HR-3E:A
designator U?, comment MT47H64M16HR-3E:A
16 Meg x 16 x 8 banks DDR2 SDRAM
footprint FBGA84 (FBGA, 84-Leads, Body 14.0x11.5mm,  Pitch 0.80mm)
pins: A1 VDD (power), A2 NC, A3 VSS (power), A7 VSSQ (power), A8 UDQS# (io), A9 VDDQ (power), B1 DQ14 (io), B2 VSSQ (power), B3 UDM (io), B7 UDQS (io), B8 VSSQ (power), B9 DQ15 (io), C1 VDDQ (power), C2 DQ9 (io), C3 VDDQ (power), C7 VDDQ (power), C8 DQ8 (io), C9 VDDQ (power), D1 DQ12 (io), D2 VSSQ (power), D3 DQ11 (io), D7 DQ10 (io), D8 VSSQ (power), D9 DQ13 (io), E1 VDD (power), E2 NC, E3 VSS (power), E7 VSSQ (power), E8 LDQS# (io), E9 VDDQ (power), F1 DQ6 (io), F2 VSSQ (power), F3 LDM (io), F7 LDQS (io), F8 VSSQ (power), F9 DQ7 (io), G1 VDDQ (power), G2 DQ1 (io), G3 VDDQ (power), G7 VDDQ (power), G8 DQ0 (io), G9 VDDQ (power), H1 DQ4 (io), H2 VSSQ (power), H3 DQ3 (io), H7 DQ2 (io), H8 VSSQ (power), H9 DQ5 (io), J1 VDDL (power), J2 VREF (power), J3 VSS (power), J7 VSSDL (power), J8 CK (in), J9 VDD (power), K2 CKE (in), K3 WE# (in), K7 RAS# (in), K8 CK# (in), K9 ODT (in), L1 BA2 (in), L2 BA0 (in), L3 BA1 (in), L7 CAS# (in), L8 CS# (in), M2 A10 (in), M3 A1 (in), M7 A2 (in), M8 A0 (in), M9 VDD (power), N1 VSS (power), N2 A3 (in), N3 A5 (in), N7 A6 (in), N8 A4 (in), P2 A7 (in), P3 A9 (in), P7 A11 (in), P8 A8 (in), P9 VSS (power), R1 VDD (power), R2 A12 (in), R3 RFU/(A14), R7 RFU/(A15), R8 RFU/(A13)

## IC_MT47H128M8
designator U?, comment MT47H128M8HQ
footprint BGA92C80P21X9_1900X1100X120 (BGA, 92-Leads, Body 19.0x11.0mm,  Pitch 0.80mm)
footprint BGA60C80P11X9_1150X800X120 (BGA, 60-Leads, Body 11.5x8.0mm,  Pitch 0.80mm)
pins: D1 VDD (power), D3 VSS (power), D7 VSSQ (power), D9 VDDQ (power), H1 VDD (power), H2 ~{RDQS} (io), H3 VSS (power), H7 VSSQ (power), H8 ~{DQS} (io), H9 VDDQ (power), J1 DQ6 (io), J2 VSSQ (power), J3 DM/RDQS (io), J7 DQS (io), J8 VSSQ (power), J9 DQ7 (io), K1 VDDQ (power), K2 DQ1 (io), K3 VDDQ (power), K7 VDDQ (power), K8 DQ0 (io), K9 VDDQ (power), L1 DQ4 (io), L2 VSSQ (power), L3 DQ3 (io), L7 DQ2 (io), L8 VSSQ (power), L9 DQ5 (io), M1 VDDL (power), M2 VREF (power), M3 VSS (power), M7 VSSDL (power), M8 CK (in), M9 VDD (power), N2 CKE (in), N3 ~{WE} (in), N7 ~{RAS} (in), N8 ~{CK} (in), N9 ODT (power), P1 BA2 (in), P2 BA0 (in), P3 BA1 (in), P7 ~{CAS} (in), P8 ~{CS} (in), R2 A10 (in), R3 A1 (in), R7 A2 (in), R8 A0 (in), R9 VDD (power), T1 VSS (power), T2 A3 (in), T3 A5 (in), T7 A6 (in), T8 A4 (in), U2 A7 (in), U3 A9 (in), U7 A11 (in), U8 A8 (in), U9 VSS (power), V1 VDD (power), V2 A12 (in), V3 RFU/A14, V7 RFU/A15, V8 A13 (in)

## IC_MT47H128M16HG-37E:A
designator U?, comment MT47H128M16HG-37E:A
16 Meg x 16 x 8 banks DDR2 SDRAM
footprint FBGA84 (FBGA, 84-Leads, Body 14.0x11.5mm,  Pitch 0.80mm)
pins: A1 VDD (power), A2 NC, A3 VSS (power), A7 VSSQ (power), A8 UDQS# (io), A9 VDDQ (power), B1 DQ14 (io), B2 VSSQ (power), B3 UDM (in), B7 UDQS (io), B8 VSSQ (power), B9 DQ15 (io), C1 VDDQ (power), C2 DQ9 (io), C3 VDDQ (power), C7 VDDQ (power), C8 DQ8 (io), C9 VDDQ (power), D1 DQ12 (io), D2 VSSQ (power), D3 DQ11 (io), D7 DQ10 (io), D8 VSSQ (power), D9 DQ13 (io), E1 VDD (power), E2 NC, E3 VSS (power), E7 VSSQ (power), E8 LDQS# (io), E9 VDDQ (power), F1 DQ6 (io), F2 VSSQ (power), F3 LDM (in), F7 LDQS (io), F8 VSSQ (power), F9 DQ7 (io), G1 VDDQ (power), G2 DQ1 (io), G3 VDDQ (power), G7 VDDQ (power), G8 DQ0 (io), G9 VDDQ (power), H1 DQ4 (io), H2 VSSQ (power), H3 DQ3 (io), H7 DQ2 (io), H8 VSSQ (power), H9 DQ5 (io), J1 VDDL (power), J2 VREF (power), J3 VSS (power), J7 VSSDL (power), J8 CK (in), J9 VDD (power), K2 CKE (in), K3 WE# (in), K7 RAS# (in), K8 CK# (in), K9 ODT (in), L1 BA2 (in), L2 BA0 (in), L3 BA1 (in), L7 CAS# (in), L8 CS# (in), M2 A10 (in), M3 A1 (in), M7 A2 (in), M8 A0 (in), M9 VDD (power), N1 VSS (power), N2 A3 (in), N3 A5 (in), N7 A6 (in), N8 A4 (in), P2 A7 (in), P3 A9 (in), P7 A11 (in), P8 A8 (in), P9 VSS (power), R1 VDD (power), R2 A12 (in), R3 RFU/(A14) (in), R7 RFU/(A15) (in), R8 A13 (in)

## IC_MT48LC32M8A2TG-75 L
designator U?, comment MT48LC32M8A2TG-75 L
256Mb Synchronous High-Speed CMOS DRAM, 32Mb x 8Bit x 4 Banks, 54-Pin TSOP, Commercial, Low Power; CycleTime: 7.5ns @ CL = 3 (PC133); RowAddress: 8K (A0-A12); ColumnAddress: 1K (A0-A9)
footprint TSOP2-54_N (SOP, 54-Leads, Body 22.2x10.16mm, Pitch 0.8mm, IPC Medium Density)
footprint TSOP2-54_L (SOP, 54-Leads, Body 22.2x10.16mm, Pitch 0.8mm, IPC High Density)
footprint TSOP2-54_M (SOP, 54-Leads, Body 22.2x10.16mm, Pitch 0.8mm, IPC Low Density)
pins: 1 VDD (power) "Power Supply", 2 DQ0 (io) "Data Input/Output 0", 3 VDDQ (power) "DQ Power", 4 DQ1 "No Connect", 5 DQ2 (io) "Data Input/Output 1", 6 VSSQ (power) "DQ Ground", 7 DQ3 "No Connect", 8 DQ4 (io) "Data Input/Output 2", 9 VDDQ (power) "DQ Power", 10 DQ5 "No Connect", 11 DQ6 (io) "Data Input/Output 3", 12 VSSQ (power) "DQ Ground", 13 DQ7 "No Connect", 14 VDD (power) "Power Supply", 15 DQML "No Connect", 16 ~{WE} (in) "Command Input", 17 ~{CAS} (in) "Command Input", 18 ~{RAS} (in) "Command Input", 19 ~{CS} (in) "Chip Select", 20 BA0 (in) "Bank Address Input 0", 21 BA1 (in) "Bank Address Input 1", 22 A10 (in) "Address Input 10", 23 A0 (in) "Address Input 0", 24 A1 (in) "Address Input 1", 25 A2 (in) "Address Input 2", 26 A3 (in) "Address Input 3", 27 VDD (power) "Power Supply", 28 VSS (power) "Ground", 29 A4 (in) "Address Input 4", 30 A5 (in) "Address Input 5", 31 A6 (in) "Address Input 6", 32 A7 (in) "Address Input 7", 33 A8 (in) "Address Input 8", 34 A9 (in) "Address Input 9", 35 A11 (in) "Address Input 11", 36 A12 (in) "Address Input 12", 37 CKE (in) "Clock Enable", 38 CLK (in) "Clock", 39 DQMH (in) "Input/Output Mask", 40 NC "No Connect", 41 VSS (power) "Ground", 42 DQ8 "No Connect", 43 VDDQ (power) "DQ Power", 44 DQ9 (io) "Data Input/Output 4", 45 DQ10 "No Connect", 46 VSSQ (power) "DQ Ground", 47 DQ11 (io) "Data Input/Output 5", 48 DQ12 "No Connect", 49 VDDQ (power) "DQ Power", 50 DQ13 (io) "Data Input/Output 6", 51 DQ14 "No Connect", 52 VSSQ (power) "DQ Ground", 53 DQ15 (io) "Data Input/Output 7", 54 VSS (power) "Ground"

## IC_NANDFlash_HY27UF081G2M
designator U?
Hynix; 1Gbit (128Mx8bit) NAND Flash; TSOP type1
footprint TSOP_Type1_50P2000X120-48N (TSOP Type 1, 48-Leads, Body 12.1x18.5mm (max), Pitch 0.50mm, IPC Medium Density)
pins: 7 R/~{B} (oc), 8 ~{RE} (in), 9 ~{CE} (in), 12 VCC (power), 13 VSS (power), 16 CLE (in), 17 ALE (in), 18 ~{WE} (in), 19 ~{WP} (in), 29 I/O0 (io), 30 I/O1 (io), 31 I/O2 (io), 32 I/O3 (io), 36 VSS (power), 37 VCC (power), 38 PRE/VSS2 (power), 41 I/O4 (io), 42 I/O5 (io), 43 I/O6 (io), 44 I/O7 (io)

## IC_PCF2123
designator U?, comment PCF2123TS/1
SPI Real time clock/calendar
footprint TSSOP-14
pins: 1 OSCI (hiz), 2 OSCO (hiz), 3 NC, 4 TEST (in), 5 ~{INT}, 6 CE (in), 7 VSS (power), 8 SDO (out), 9 SDI (in), 10 SCL (in), 11 NC, 12 CLKOE (in), 13 CLKOUT (out), 14 VDD (power)

## IC_PI74LPT16244
designator U?, comment PI74LPT16244
3.3V, 16-Bit Buffer/Line Driver
pins: 1 ~{1OE}, 2 1Y0, 3 1Y1, 4 GND, 5 1Y2, 6 1Y3, 7 VCC, 8 2Y0, 9 2Y1, 10 GND, 11 2Y2, 12 2Y3, 13 3Y0, 14 3Y1, 15 GND, 16 3Y2, 17 3Y3, 18 VCC, 19 4Y0, 20 4Y1, 21 GND, 22 4Y2, 23 4Y3, 24 ~{4OE}, 25 ~{3OE}, 26 4A3, 27 4A2, 28 GND, 29 4A1, 30 4A0, 31 VCC, 32 3A3, 33 3A2, 34 GND, 35 3A1, 36 3A0, 37 2A3, 38 2A2, 39 GND, 40 2A1, 41 2A0, 42 VCC, 43 1A3, 44 1A2, 45 GND, 46 1A1, 47 1A0, 48 ~{2OE}

## IC_PIC24FJ64GA006
designator U?
64-Pin General Purpose,  16-Bit Flash Microcontroller
footprint TQFP50P1200X1200X120-64N (TQFP, 64-Leads, Body 12.0x12.0mm (max), Pitch 0.50mm, IPC Medium Density)
pins: 1 PMD5/RE5, 2 PMD6/RE6, 3 PMD7/RE7, 4 SCK2/CN8/RG6, 5 SDI2/CN9/RG7, 6 SDO2/CN10/RG8, 7 ~{MCLR}, 8 ~{SS2}/CN11/RG9, 9 Vss, 10 Vdd, 11 CN7/RB5, 12 CN6/RB4, 13 CN5/RB3, 14 ~{SS1}/CN4/RB2, 15 PGC1/CN3/RB1, 16 PGD1/CN2/RB0, 17 PGC2/RB6, 18 PGD2/RB7, 19 AVdd, 20 AVss, 21 ~{U2CTS}/RB8, 22 RB9, 23 RB10, 24 RB11, 25 Vss, 26 Vdd, 27 RB12, 28 RB13, 29 ~{U2RTS}/RB14, 30 PMA0/CN12/RB15, 31 U2RX/SDA2/CN17/RF4, 32 U2TX/SCL2/CN18/RF5, 33 U1TX/SDO1/RF3, 34 U1RX/SDI1/RF2, 35 ~{U1RTS}/SCK1/RF6, 36 SDA1/RG3, 37 SCL1/RG2, 38 Vdd, 39 OSC1/RC12, 40 OSC2/RC15, 41 Vss, 42 RTCC/RD8, 43 ~{U1CTS}/RD9, 44 PMCS2/RD10, 45 PMCS1/RD11, 46 RD0, 47 SOSCI/CN1/RC13, 48 SOSCO/CN0/RC14, 49 RD1, 50 RD2, 51 RD3, 52 PMWR/CN13/RD4, 53 PMRD/CN14/RD5, 54 CN15/RD6, 55 CN16/RD7, 56 Vcap/Vddcore, 57 ENVREG, 58 RF0, 59 RF1, 60 PMD0/RE0, 61 PMD1/RE1, 62 PMD2/RE2, 63 PMD3/RE3, 64 PMD4/RE4

## IC_REF195ESZ
designator U?, comment REF195ESZ
Precision Micropower,  Low Dropout Voltage Reference; 5.0V; Analog Devices; Manufacturer: Analog Devices Inc; Note: IC VOLT REFERENCE LDO 5.0V 8SOIC
pins: 1 TP, 2 VIN, 3 ~{SLEEP}, 4 GND, 5 TP, 6 OUT, 7 NC, 8 NC

## IC_RT9502
designator U?, comment RT9592PQW
Linear Single Cell Li-Ion Battery Charger IC with  Dual Input Supply
footprint DFN50P300X300X80-10N (DFN, 10-Leads, Body 3.0x3.0mm (max), Pitch 0.50mm, IPC Medium Density)
pins: 1 AC1 (power), 2 USB (power), 3 ~{CHG_S}, 4 ~{PGOOD}, 5 GND (power), 6 ISETA, 7 ISETU, 8 ~{EN} (in), 9 TS (in), 10 BATT (out), 11 hidden to GND

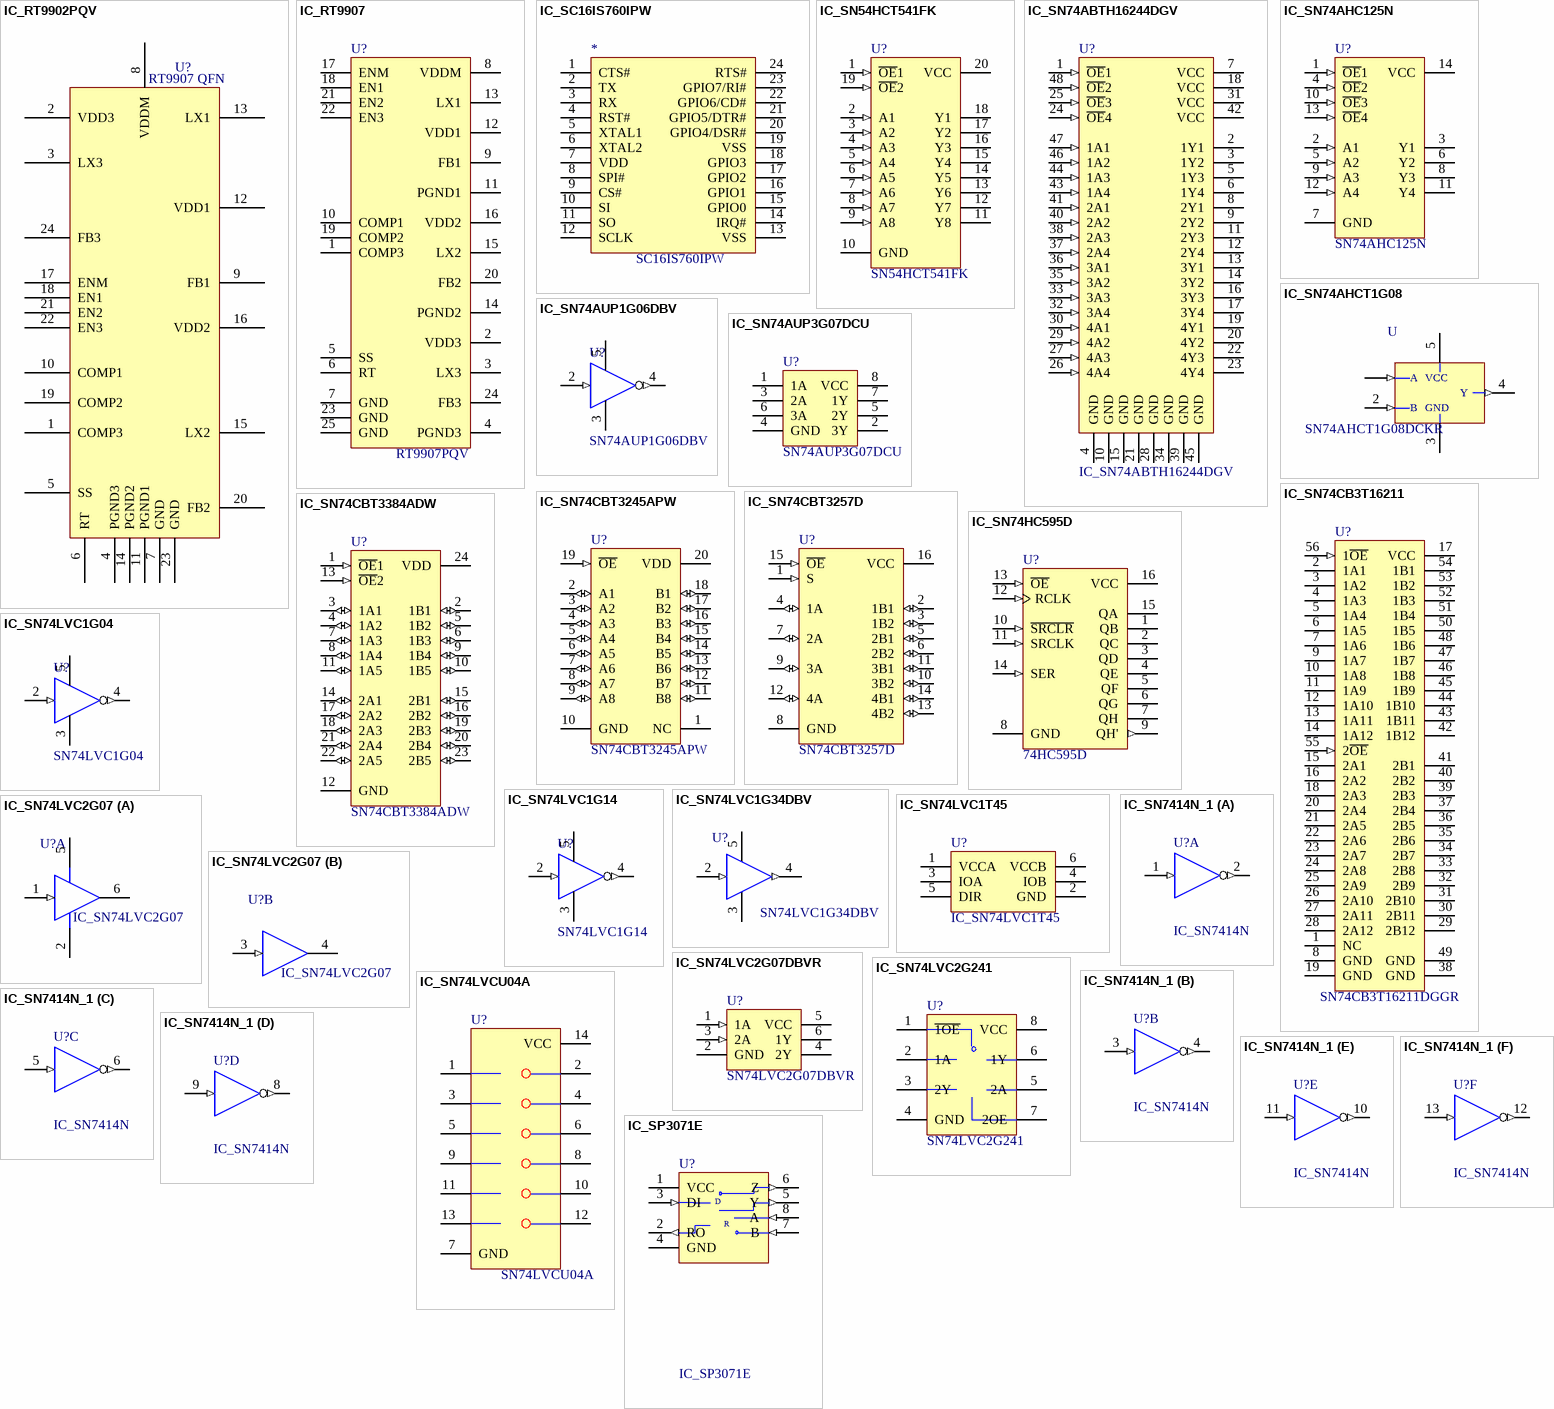
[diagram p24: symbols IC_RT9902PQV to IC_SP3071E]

## IC_RT9902PQV
designator U?, comment RT9907 QFN
RT9902PQV QFN-32L 5X5; Part Number: temp_226_dd26; Component_Name: 4 CHANNEL DC/DC CONVERTERS IC; Data_Sheet: K:\DataSheet\06-IC\temp_226_dd26.zip; Device: qfn_32p_20_197x197_pad_sirf; QVL_Approve: N
footprint RT9907-1
footprint QFN24
pins: 1 COMP3, 2 VDD3, 3 LX3, 4 PGND3, 5 SS, 6 RT, 7 GND, 8 VDDM, 9 FB1, 10 COMP1, 11 PGND1, 12 VDD1, 13 LX1, 14 PGND2, 15 LX2, 16 VDD2, 17 ENM, 18 EN1, 19 COMP2, 20 FB2, 21 EN2, 22 EN3, 23 GND, 24 FB3

## IC_RT9907
designator U?, comment RT9907PQV
3 Channel DC/DC Converters IC with  High-Efficiency Step-up and Step-down
footprint QFN50P400X400X100-24N (QFN, 24-Leads, Body 4.1x4.1mm (max), Pitch 0.50mm, IPC Medium Density)
pins: 1 COMP3, 2 VDD3, 3 LX3, 4 PGND3, 5 SS, 6 RT, 7 GND, 8 VDDM, 9 FB1, 10 COMP1, 11 PGND1, 12 VDD1, 13 LX1, 14 PGND2, 15 LX2, 16 VDD2, 17 ENM, 18 EN1, 19 COMP2, 20 FB2, 21 EN2, 22 EN3, 23 GND, 24 FB3, 25 GND

## IC_SC16IS760IPW
designator SC16IS760IPW
IC UART 64BYTE 24TSSOP
footprint TSSOP65P640X110-24N (TSSOP, 24-Leads, Body 7.9x4.5mm (max), Pitch 0.65mm, IPC Medium Density)
pins: 1 CTS#, 2 TX, 3 RX, 4 RST#, 5 XTAL1, 6 XTAL2, 7 VDD, 8 SPI#, 9 CS#, 10 SI, 11 SO, 12 SCLK, 13 VSS, 14 IRQ#, 15 GPIO0, 16 GPIO1, 17 GPIO2, 18 GPIO3, 19 VSS, 20 GPIO4/DSR#, 21 GPIO5/DTR#, 22 GPIO6/CD#, 23 GPIO7/RI#, 24 RTS#

## IC_SN54HCT541FK
designator U?, comment SN54HCT541FK
Octal Buffer and Line Driver with 3-State Outputs
signal-integrity model SN54HCT541FK
footprint SOW-20_N (SOIC, 20-Leads, Body 12.8x7.5mm, Pitch 1.27mm, IPC Medium Density)
pins: 1 ~{OE}1 (in), 2 A1 (in), 3 A2 (in), 4 A3 (in), 5 A4 (in), 6 A5 (in), 7 A6 (in), 8 A7 (in), 9 A8 (in), 10 GND (power), 11 Y8 (hiz), 12 Y7 (hiz), 13 Y6 (hiz), 14 Y5 (hiz), 15 Y4 (hiz), 16 Y3 (hiz), 17 Y2 (hiz), 18 Y1 (hiz), 19 ~{OE}2 (in), 20 VCC (power)

## IC_SN74ABTH16244DGV
designator U?
16-Bit Buffer/Driver with 3-State Outputs
footprint DGV048_N (TSSOP, 48-Leads, Body 9.7x4.4mm, Pitch 0.4mm, IPC Medium Density)
footprint DGV048_M (TSSOP, 48-Leads, Body 9.7x4.4mm, Pitch 0.4mm, IPC Low Density)
3D model DGV048 (48-Pin Thin Shrink Small Outline Package 0.4 mm Pitch)
pins: 1 ~{OE}1 (in), 2 1Y1 (hiz), 3 1Y2 (hiz), 4 GND (power), 5 1Y3 (hiz), 6 1Y4 (hiz), 7 VCC (power), 8 2Y1 (hiz), 9 2Y2 (hiz), 10 GND (power), 11 2Y3 (hiz), 12 2Y4 (hiz), 13 3Y1 (hiz), 14 3Y2 (hiz), 15 GND (power), 16 3Y3 (hiz), 17 3Y4 (hiz), 18 VCC (power), 19 4Y1 (hiz), 20 4Y2 (hiz), 21 GND (power), 22 4Y3 (hiz), 23 4Y4 (hiz), 24 ~{OE}4 (in), 25 ~{OE}3 (in), 26 4A4 (in), 27 4A3 (in), 28 GND (power), 29 4A2 (in), 30 4A1 (in), 31 VCC (power), 32 3A4 (in), 33 3A3 (in), 34 GND (power), 35 3A2 (in), 36 3A1 (in), 37 2A4 (in), 38 2A3 (in), 39 GND (power), 40 2A2 (in), 41 2A1 (in), 42 VCC (power), 43 1A4 (in), 44 1A3 (in), 45 GND (power), 46 1A2 (in), 47 1A1 (in), 48 ~{OE}2 (in)

## IC_SN74AHC125N
designator U?, comment SN74AHC125N
Quadruple Bus Buffer Gate with 3-State Outputs
3D model N014 (DIP; 14 Leads; Row Spacing 7.62 mm; Pitch 2.54 mm)
signal-integrity model SN74AHC125N
footprint SO-14_N (14-Pin Small Outline Integrated Circuit 1.27 mm Pitch, IPC Medium Density)
pins: 1 ~{OE}1 (in), 2 A1 (in), 3 Y1 (hiz), 4 ~{OE}2 (in), 5 A2 (in), 6 Y2 (hiz), 7 GND (power), 8 Y3 (hiz), 9 A3 (in), 10 ~{OE}3 (in), 11 Y4 (hiz), 12 A4 (in), 13 ~{OE}4 (in), 14 VCC (power)

## IC_SN74AHCT1G08
designator U, comment SN74AHCT1G08DCKR
pins: 1 (in), 2 (in), 3, 4 (out), 5

## IC_SN74AUP1G06DBV
designator U?, comment SN74AUP1G06DBV
Inverter, Single
footprint SOT23-5AL (SOT23, 5-Leads, Body 2.9x1.6mm, Pitch 0.95mm, Lead Span 2.8mm)
3D model N014 (DIP; 14 Leads; Row Spacing 7.62 mm; Pitch 2.54 mm)
signal-integrity model SN7414N
pins: 2 A (in), 3 GND (power), 4 Y (out), 5 VCC (power)
1 alternate drawing of the same symbol

## IC_SN74AUP3G07DCU
designator U?, comment SN74AUP3G07DCU
LOW-POWER TRIPLE BUFFER/DRIVER WITH OPEN-DRAIN OUTPUTS
footprint SSOP50P310X90-8N (SSOP, 8-Leads, Body 2.1x2.4mm (max), Pitch 0.50mm, IPC Medium Density)
pins: 1 1A, 2 3Y, 3 2A, 4 GND, 5 2Y, 6 3A, 7 1Y, 8 VCC

## IC_SN74CB3T16211
designator U?, comment SN74CB3T16211DGGR
24-bit, FET bus switch, 2.5V/3.3V Low Voltage with 5V tolerant level shifter
pins: 1 NC, 2 1A1, 3 1A2, 4 1A3, 5 1A4, 6 1A5, 7 1A6, 8 GND (power), 9 1A7, 10 1A8, 11 1A9, 12 1A10, 13 1A11, 14 1A12, 15 2A1, 16 2A2, 17 VCC (power), 18 2A3, 19 GND (power), 20 2A4, 21 2A5, 22 2A6, 23 2A7, 24 2A8, 25 2A9, 26 2A10, 27 2A11, 28 2A12, 29 2B12, 30 2B11, 31 2B10, 32 2B9, 33 2B8, 34 2B7, 35 2B6, 36 2B5, 37 2B4, 38 GND (power), 39 2B3, 40 2B2, 41 2B1, 42 1B12, 43 1B11, 44 1B10, 45 1B9, 46 1B8, 47 1B7, 48 1B6, 49 GND (power), 50 1B5, 51 1B4, 52 1B3, 53 1B2, 54 1B1, 55 2~{OE} (in), 56 1~{OE} (in)

## IC_SN74CBT3245APW
designator U?, comment SN74CBT3245APW
Octal FET Bus Switch
3D model PW020 (Shrink Small Outline; 20 Leads; Body Width 4.4 mm; Pitch 0.65 mm)
footprint TSOP65P640X120-20N (TSOP, 20-Leads, Body 6.6x4.5mm (max), Pitch 0.65mm, IPC Medium Density)
pins: 1 NC, 2 A1 (io), 3 A2 (io), 4 A3 (io), 5 A4 (io), 6 A5 (io), 7 A6 (io), 8 A7 (io), 9 A8 (io), 10 GND (power), 11 B8 (io), 12 B7 (io), 13 B6 (io), 14 B5 (io), 15 B4 (io), 16 B3 (io), 17 B2 (io), 18 B1 (io), 19 ~{OE} (in), 20 VDD (power)

## IC_SN74CBT3257D
designator U?, comment SN74CBT3257D
4-Bit 1-of-2 FET Multiplexer/Demultiplexer
3D model D016 (16-Pin Small Outline Integrated Circuit 1.27 mm Pitch)
footprint SO-16_N (16-Pin Small Outline Integrated Circuit 1.27 mm Pitch, IPC Medium Density)
pins: 1 S (in), 2 1B1 (io), 3 1B2 (io), 4 1A (io), 5 2B1 (io), 6 2B2 (io), 7 2A (io), 8 GND (power), 9 3A (io), 10 3B2 (io), 11 3B1 (io), 12 4A (io), 13 4B2 (io), 14 4B1 (io), 15 ~{OE} (in), 16 VCC (power)

## IC_SN74CBT3384ADW
designator U?, comment SN74CBT3384ADW
10-Bit FET Bus Switch
3D model DW024 (24-Pin Plastic Small Outline Integrated Circuit 1.27 mm Pitch)
footprint TSOP65P640X120-24N (TSOP, 24-Leads, Body 7.9x4.5mm (max), Pitch 0.65mm, IPC Medium Density)
pins: 1 ~{OE}1 (in), 2 1B1 (io), 3 1A1 (io), 4 1A2 (io), 5 1B2 (io), 6 1B3 (io), 7 1A3 (io), 8 1A4 (io), 9 1B4 (io), 10 1B5 (io), 11 1A5 (io), 12 GND (power), 13 ~{OE}2 (in), 14 2A1 (io), 15 2B1 (io), 16 2B2 (io), 17 2A2 (io), 18 2A3 (io), 19 2B3 (io), 20 2B4 (io), 21 2A4 (io), 22 2A5 (io), 23 2B5 (io), 24 VDD (power)

## IC_SN74HC595D
designator U?, comment 74HC595D
8-Bit Shift Register with 3-State Output Registers
3D model D016 (16-Pin Small Outline Integrated Circuit 1.27 mm Pitch)
signal-integrity model SN74HC595D
footprint SO-16_N (16-Pin Small Outline Integrated Circuit 1.27 mm Pitch, IPC Medium Density)
footprint TSSOP127P600-16N
pins: 1 QB (hiz), 2 QC (hiz), 3 QD (hiz), 4 QE (hiz), 5 QF (hiz), 6 QG (hiz), 7 QH (hiz), 8 GND (power), 9 QH' (out), 10 ~{SRCLR} (in), 11 SRCLK (in), 12 RCLK (in), 13 ~{OE} (in), 14 SER (in), 15 QA (hiz), 16 VCC (power)

## IC_SN74LVC1G04
designator U?, comment SN74LVC1G04
Inverter, Single
footprint SOT23-5AL (SOT23, 5-Leads, Body 2.9x1.6mm, Pitch 0.95mm, Lead Span 2.8mm)
3D model N014 (DIP; 14 Leads; Row Spacing 7.62 mm; Pitch 2.54 mm)
signal-integrity model SN7414N
pins: 2 A (in), 3 GND (power), 4 Y (out), 5 VCC (power)
1 alternate drawing of the same symbol

## IC_SN74LVC1G14
designator U?, comment SN74LVC1G14
Hex Schmitt-Trigger Inverter, Single
footprint SOT23-5AL (SOT23, 5-Leads, Body 2.9x1.6mm, Pitch 0.95mm, Lead Span 2.8mm)
3D model N014 (DIP; 14 Leads; Row Spacing 7.62 mm; Pitch 2.54 mm)
signal-integrity model SN7414N
pins: 2 A (in), 3 GND (power), 4 Y (out), 5 VCC (power)
1 alternate drawing of the same symbol

## IC_SN74LVC1G34DBV
designator U?, comment SN74LVC1G34DBV
SINGLE BUFFER GATE; SOT-23; Manufacturer: STMicroelectronics; ManufacturerPartNo: 74V1G32STR
footprint SOT23-5AL (SOT23, 5-Leads, Body 2.9x1.6mm, Pitch 0.95mm, Lead Span 2.8mm, IPC High Density)
pins: 1 NC hidden, 2 A (in), 3 GND (power), 4 Y (out), 5 VCC (power)

## IC_SN74LVC1T45
designator U?
SINGLE-BIT DUAL-SUPPLY BUS TRANSCEIVER  WITH CONFIGURABLE VOLTAGE TRANSLATION AND 3-STATE OUTPUTS
footprint SC70-6N (SC70, 6-Leads, Body 1.3x1.7mm (max), Pitch 0.50mm, IPC Medium Density)
pins: 1 VCCA, 2 GND, 3 IOA, 4 IOB, 5 DIR, 6 VCCB

## IC_SN74LVC2G07
designator U?
Hex Schmitt-Trigger Buffer
footprint SOT23-6N (SOT23, 6-Leads, Body 3.0x3.0mm (max), Pitch 0.95mm, IPC Medium Density)
part A pins: 1 1A (in), 2 GND (power), 5 VCC (power), 6 1Y (oc)
part B pins: 3 2A (in), 4 2Y (oc)

## IC_SN74LVC2G07DBVR
designator U?, comment SN74LVC2G07DBVR
DUAL BUFFER/DRIVER WITH OPEN DRAIN OUTPUTS
footprint SOT23-6N (SOT23, 6-Leads, Body 3.0x3.0mm (max), Pitch 0.95mm, IPC Medium Density)
pins: 1 1A (in), 2 GND (power), 3 2A (in), 4 2Y (oc), 5 VCC (power), 6 1Y (oc)

## IC_SN74LVC2G241
designator U?, comment SN74LVC2G241
DUAL BUFFER/DRIVER  WITH 3-STATE OUTPUTS
footprint SOP65P-8N (SOP, 8-Leads, Body 3.2x2.9mm (max), Pitch 0.65mm, IPC Medium Density)
pins: 1 ~{1OE}, 2 1A, 3 2Y, 4 GND, 5 2A, 6 1Y, 7 2OE, 8 VCC

## IC_SN74LVCU04A
designator U?, comment SN74LVCU04A
6 X Inverter
footprint TSOP65P640X110-14N (TSOP, 14-Leads, Body 5.1x4.5mm (max), Pitch 0.65mm, IPC Medium Density)
pins: 1 1A, 2 1Y, 3 2A, 4 2Y, 5 3A, 6 3Y, 7 GND, 8 4Y, 9 4A, 10 5Y, 11 5A, 12 6Y, 13 6A, 14 VCC

## IC_SN7414N_1
designator U?, comment IC_SN7414N
Hex Schmitt-Trigger Inverter
footprint SO-14_N (14-Pin Small Outline Integrated Circuit 1.27 mm Pitch, IPC Medium Density)
3D model N014 (DIP; 14 Leads; Row Spacing 7.62 mm; Pitch 2.54 mm)
signal-integrity model SN7414N
pins on every part: 7 GND (power) hidden to GND, 14 VCC (power) hidden to VCC
part A pins: 1 A (in), 2 Y (out)
part B pins: 3 A (in), 4 Y (out)
part C pins: 5 A (in), 6 Y (out)
part D pins: 8 Y (out), 9 A (in)
part E pins: 10 Y (out), 11 A (in)
part F pins: 12 Y (out), 13 A (in)
1 alternate drawing of the same symbol

## IC_SP3071E
designator U?
5V 0.25Mbps RS422 Transceiver
footprint SO-8_N (8-Pin Small Outline Integrated Circuit 1.27 mm Pitch, IPC Medium Density)
pins: 1 VCC (power), 2 RO (out), 3 DI (in), 4 GND (power), 5 Y (out), 6 Z (out), 7 B (in), 8 A (in)

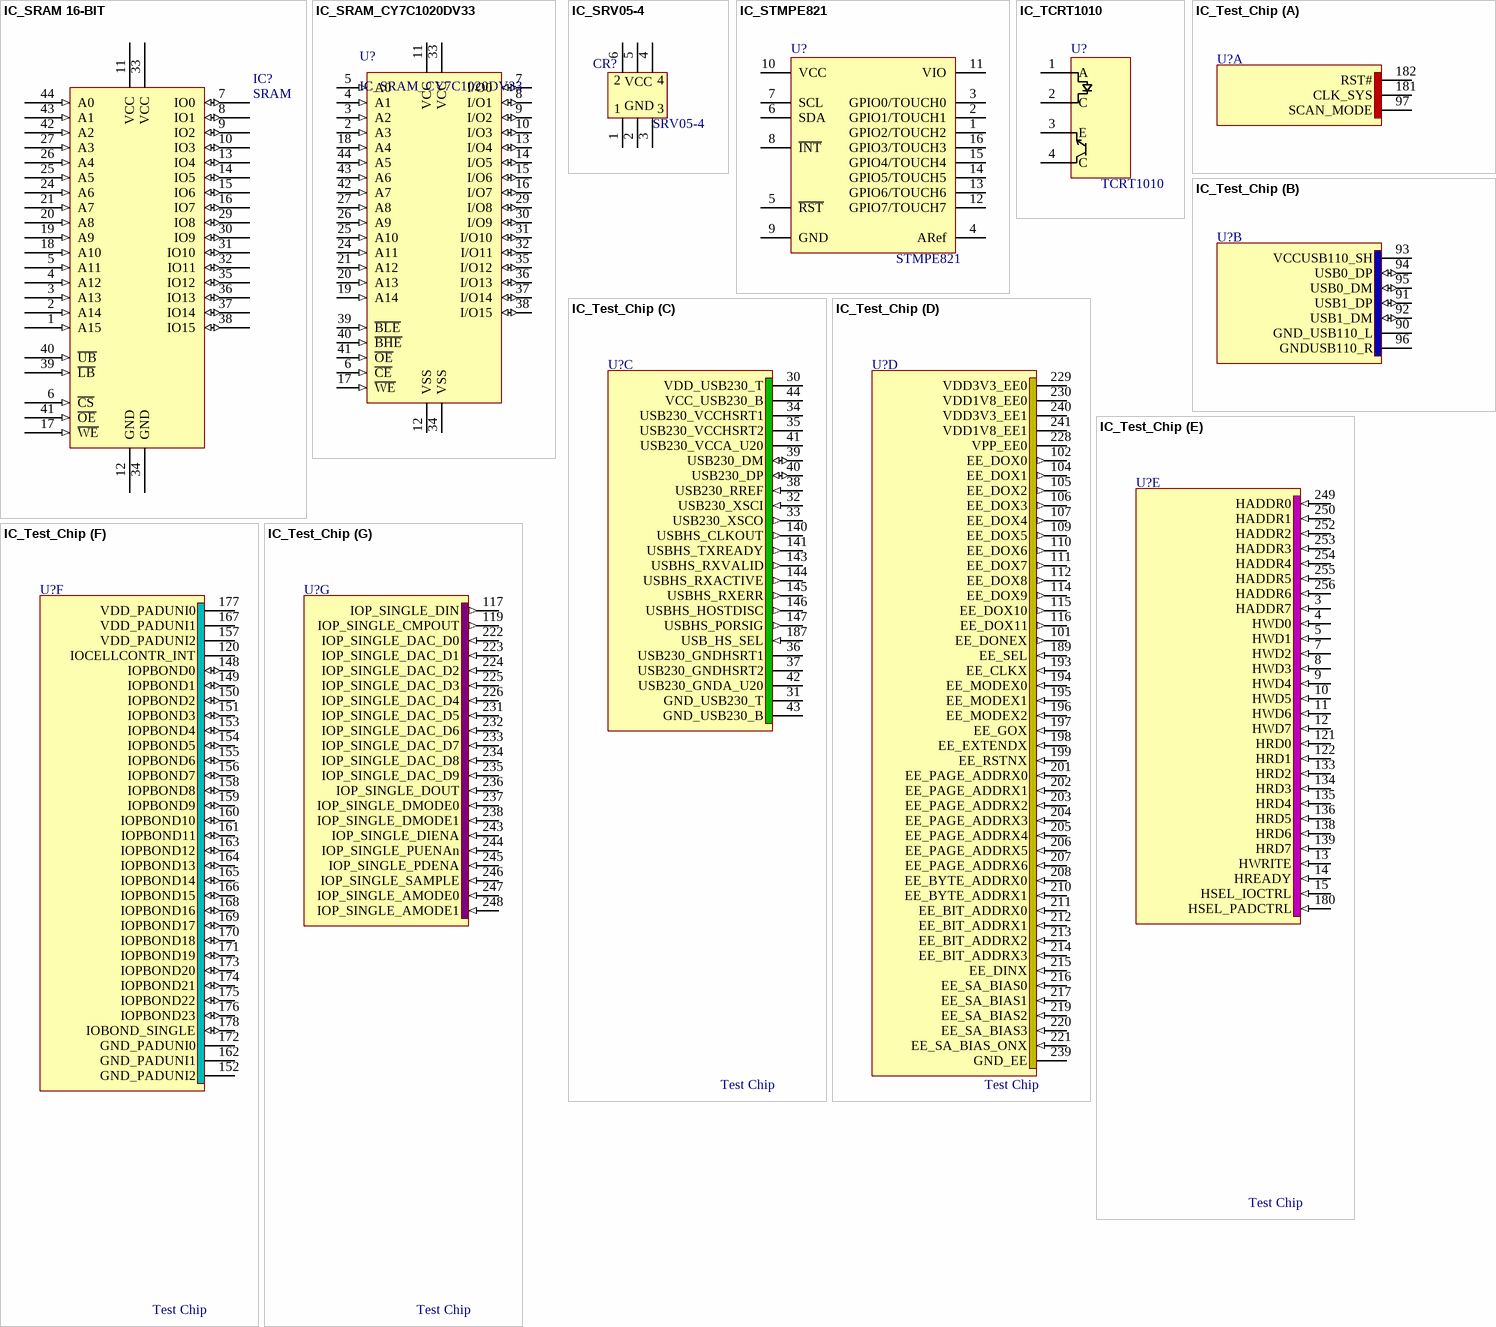
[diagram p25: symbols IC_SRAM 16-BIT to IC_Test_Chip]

## IC_SRAM 16-BIT
designator IC?, comment SRAM
16-bit S-RAM memory; TSOP Type II
footprint TSOP-Type II (Plastic TSOP Type II)
pins: 1 A15 (in), 2 A14 (in), 3 A13 (in), 4 A12 (in), 5 A11 (in), 6 ~{CS} (in), 7 IO0 (io), 8 IO1 (io), 9 IO2 (io), 10 IO3 (io), 11 VCC (power), 12 GND (power), 13 IO4 (io), 14 IO5 (io), 15 IO6 (io), 16 IO7 (io), 17 ~{WE} (in), 18 A10 (in), 19 A9 (in), 20 A8 (in), 21 A7 (in), 22 NC hidden, 23 NC hidden, 24 A6 (in), 25 A5 (in), 26 A4 (in), 27 A3 (in), 28 NC hidden, 29 IO8 (io), 30 IO9 (io), 31 IO10 (io), 32 IO11 (io), 33 VCC (power), 34 GND (power), 35 IO12 (io), 36 IO13 (io), 37 IO14 (io), 38 IO15 (io), 39 ~{LB} (in), 40 ~{UB} (in), 41 ~{OE} (in), 42 A2 (in), 43 A1 (in), 44 A0 (in)

## IC_SRAM_CY7C1020DV33
designator U?
512K (32K x 16) Static RAM
footprint TSOP_Type2_80P1180X119-44N (TSOP Type 2, 44-Leads, Body 18.5x10.3mm (max), Pitch 0.80mm, IPC Medium Density)
pins: 1 NC hidden, 2 A3 (in), 3 A2 (in), 4 A1 (in), 5 A0 (in), 6 ~{CE} (in), 7 I/O0 (io), 8 I/O1 (io), 9 I/O2 (io), 10 I/O3 (io), 11 VCC (power), 12 VSS (power), 13 I/O4 (io), 14 I/O5 (io), 15 I/O6 (io), 16 I/O7 (io), 17 ~{WE} (in), 18 A4 (in), 19 A14 (in), 20 A13 (in), 21 A12 (in), 22 NC hidden, 23 NC hidden, 24 A11 (in), 25 A10 (in), 26 A9 (in), 27 A8 (in), 28 NC hidden, 29 I/O8 (io), 30 I/O9 (io), 31 I/O10 (io), 32 I/O11 (io), 33 VCC (power), 34 VSS (power), 35 I/O12 (io), 36 I/O13 (io), 37 I/O14 (io), 38 I/O15 (io), 39 ~{BLE} (in), 40 ~{BHE} (in), 41 ~{OE} (in), 42 A7 (in), 43 A6 (in), 44 A5 (in)

## IC_SRV05-4
designator CR?, comment SRV05-4
RailClamp (R) Low Capacitance TVS Diode Array
pins: 1, 2 GND, 3, 4, 5 VCC, 6

## IC_STMPE821
designator U?, comment STMPE821
S-Touch® 8-channel capacitive touchkey controller
footprint QFN40P180X260X60-16N (QFN, 16-Leads, Body 2.7x1.9mm (max), Pitch 0.40mm, IPC Medium Density)
pins: 1 GPIO2/TOUCH2, 2 GPIO1/TOUCH1, 3 GPIO0/TOUCH0, 4 ARef, 5 ~{RST}, 6 SDA, 7 SCL, 8 ~{INT}, 9 GND, 10 VCC, 11 VIO, 12 GPIO7/TOUCH7, 13 GPIO6/TOUCH6, 14 GPIO5/TOUCH5, 15 GPIO4/TOUCH4, 16 GPIO3/TOUCH3

## IC_TCRT1010
designator U?, comment TCRT1010
SENSOR OPTO TRANS 4MM REFL THPCB; Manufacturer: Vishay Semiconductor Opto Division
signal-integrity model Connector
footprint TCRT1010
pins: 1 A, 2 C, 3 E, 4 C

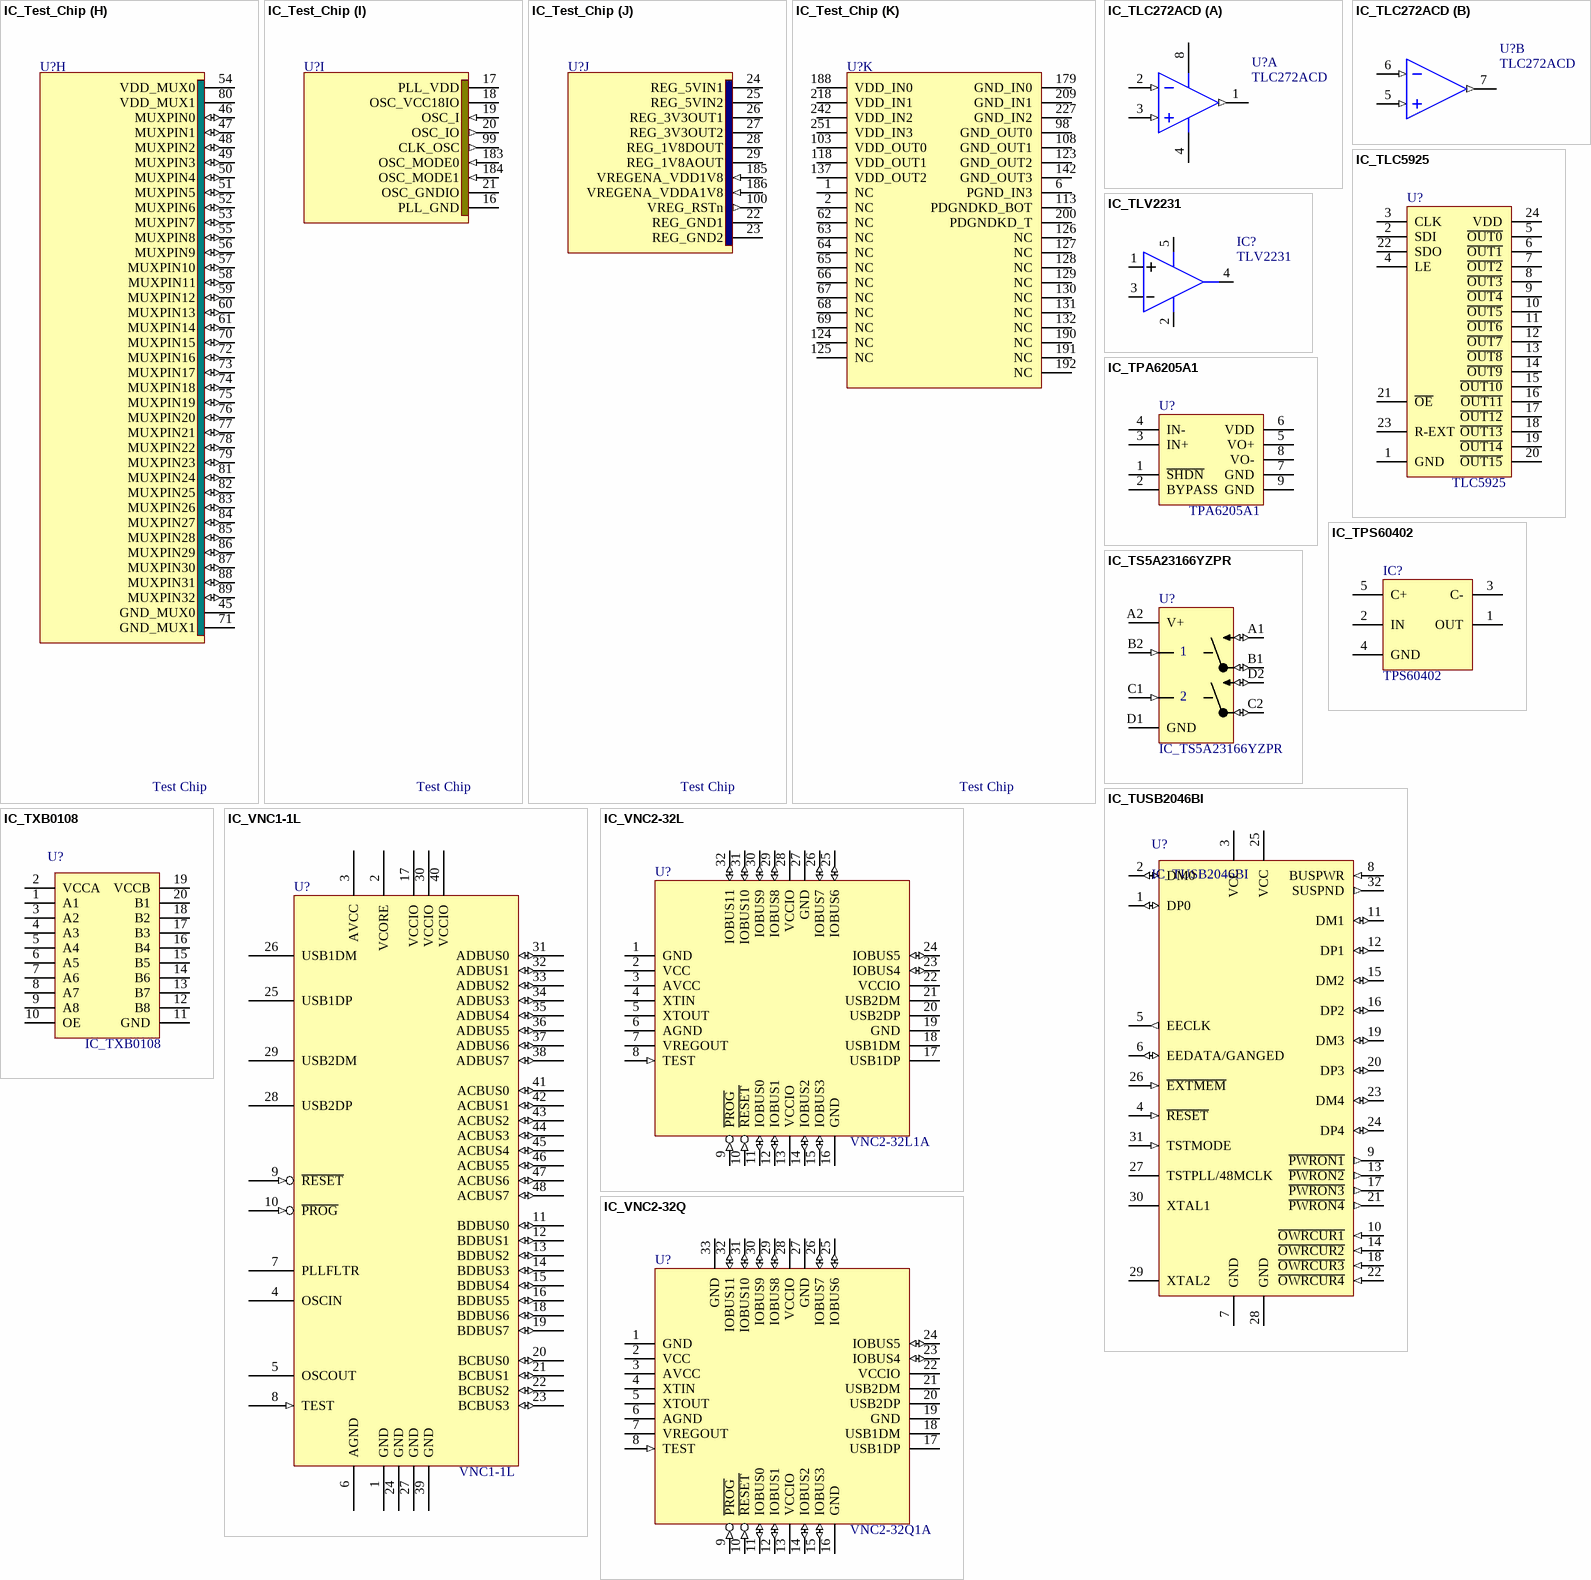
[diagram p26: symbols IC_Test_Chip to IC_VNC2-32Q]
